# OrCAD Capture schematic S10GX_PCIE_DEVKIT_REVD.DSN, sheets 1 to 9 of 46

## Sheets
1 Title, Note, Block Diagram: title: Stratix 10 GX FPGA Development Kit; rev: D1; note: 150-0321309-D1      (6XX-44484R)
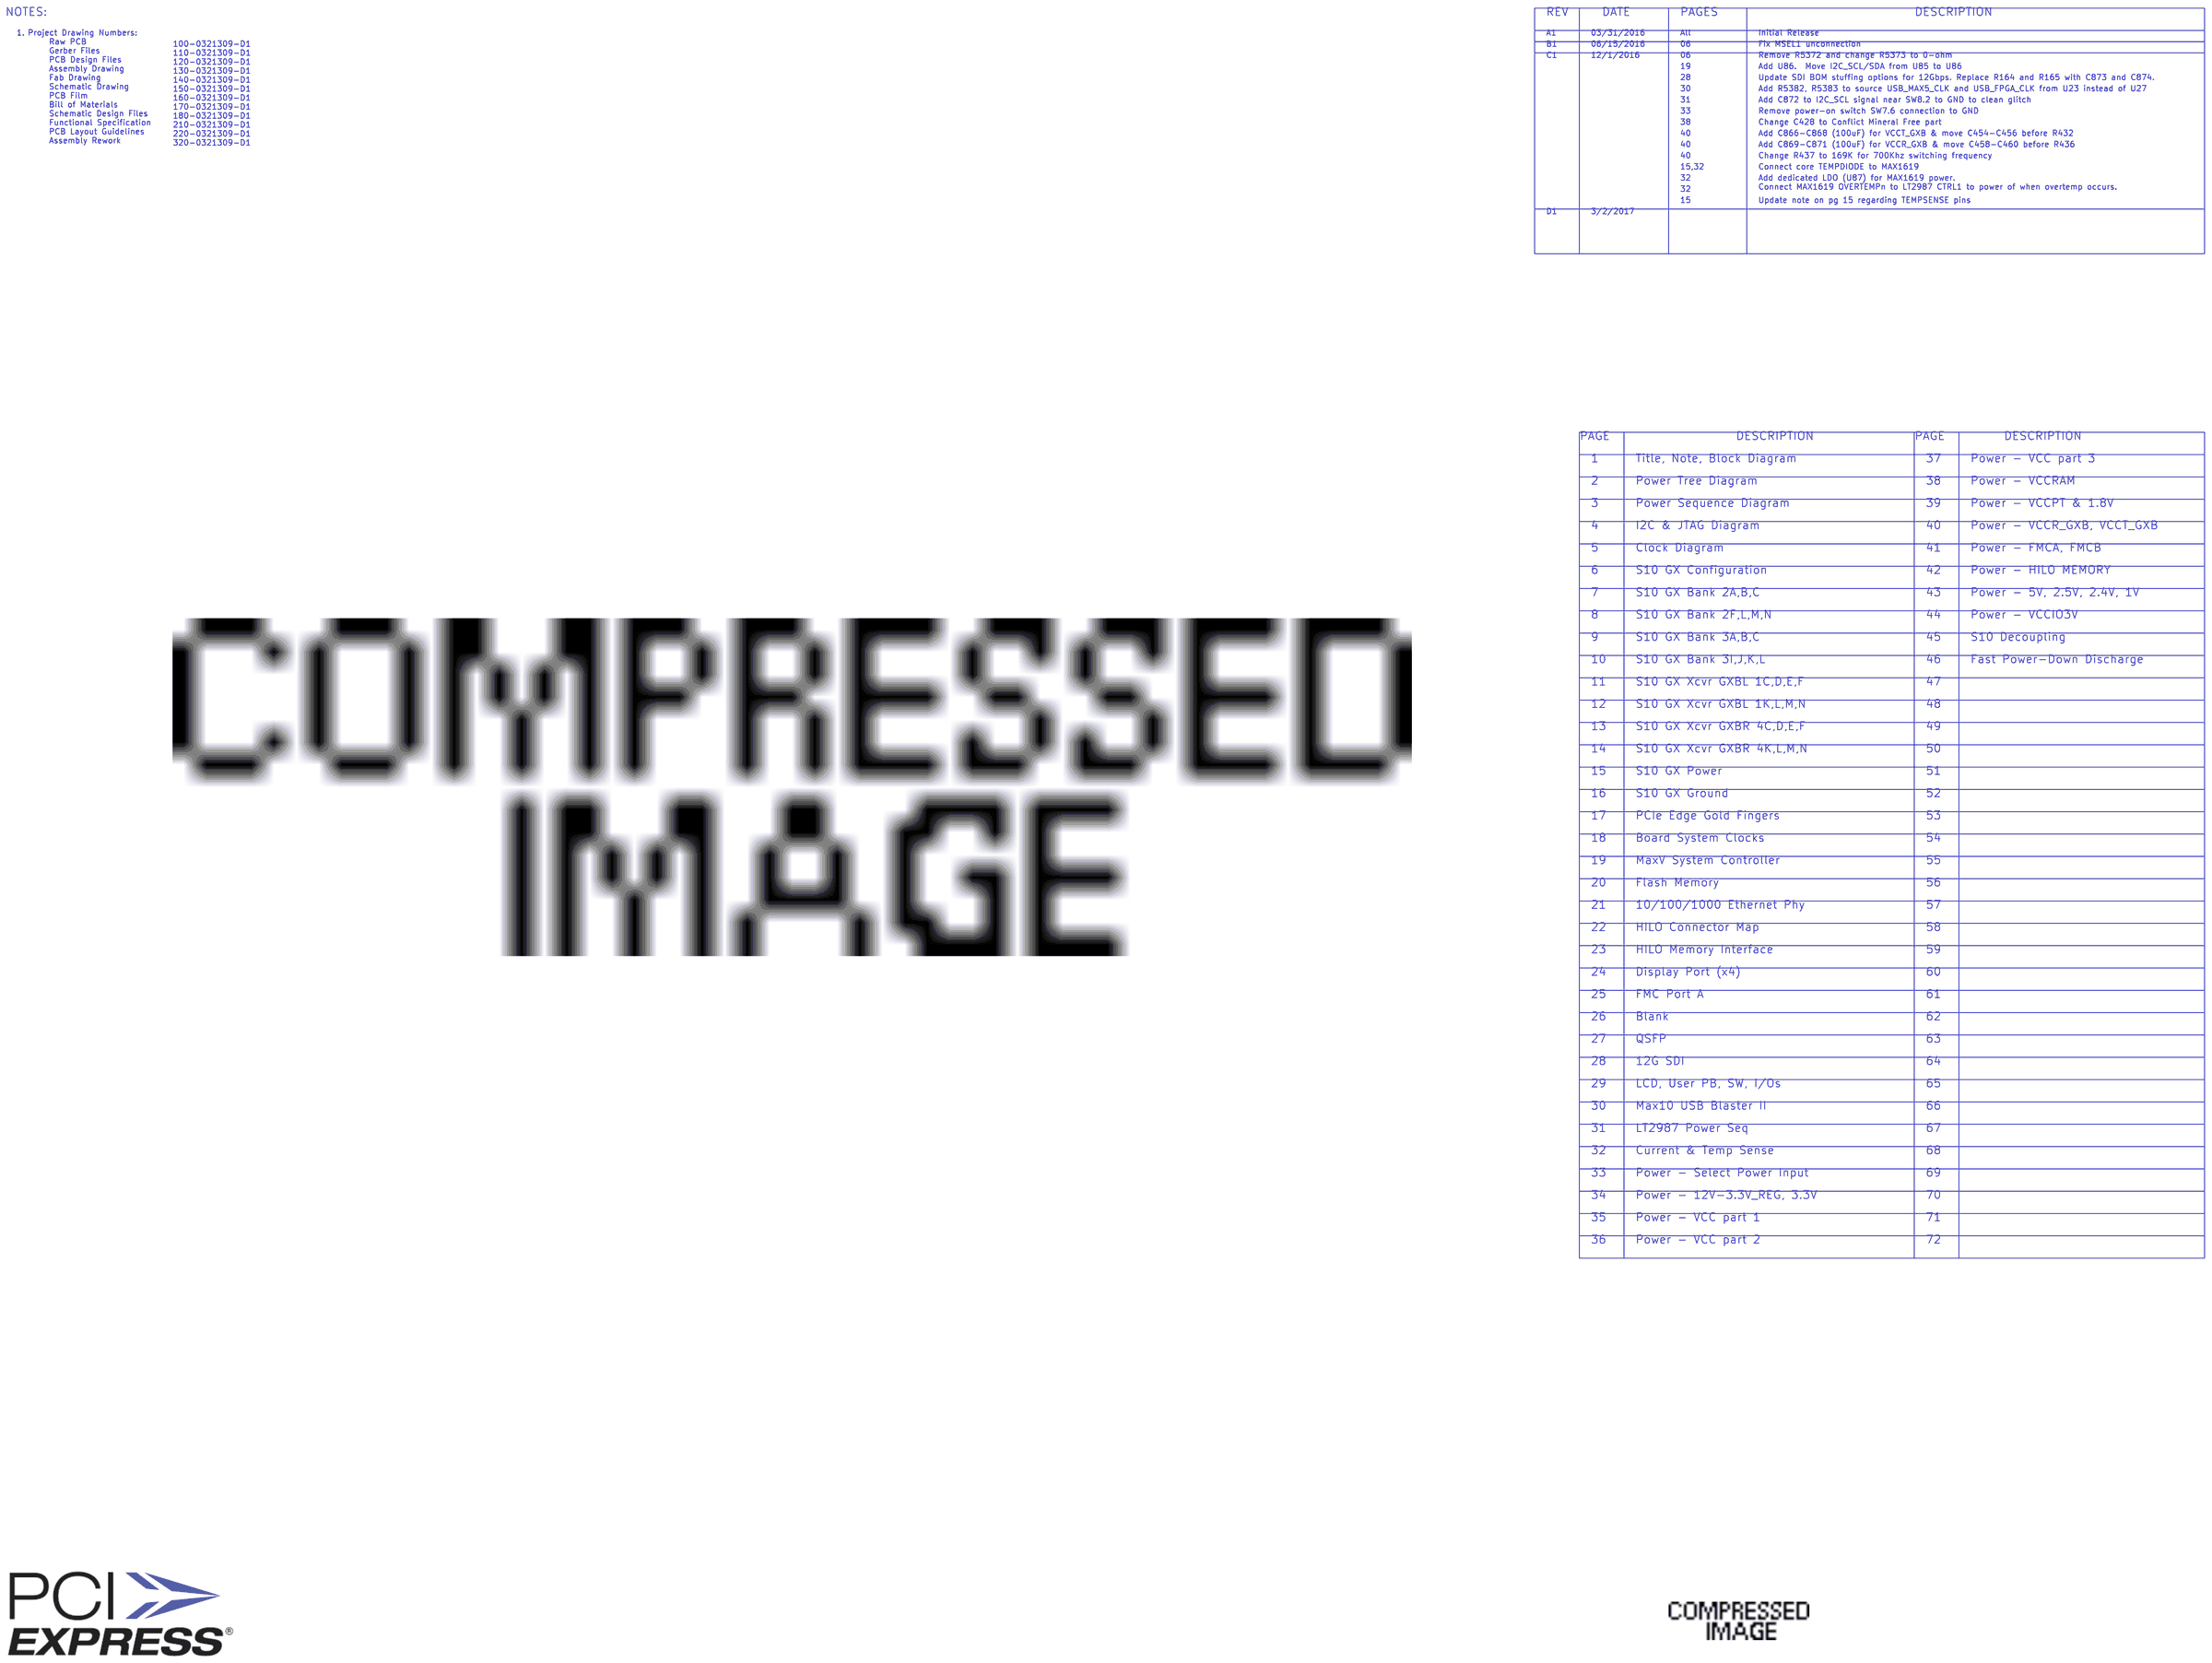
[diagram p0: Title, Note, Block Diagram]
2 Power Tree Diagram
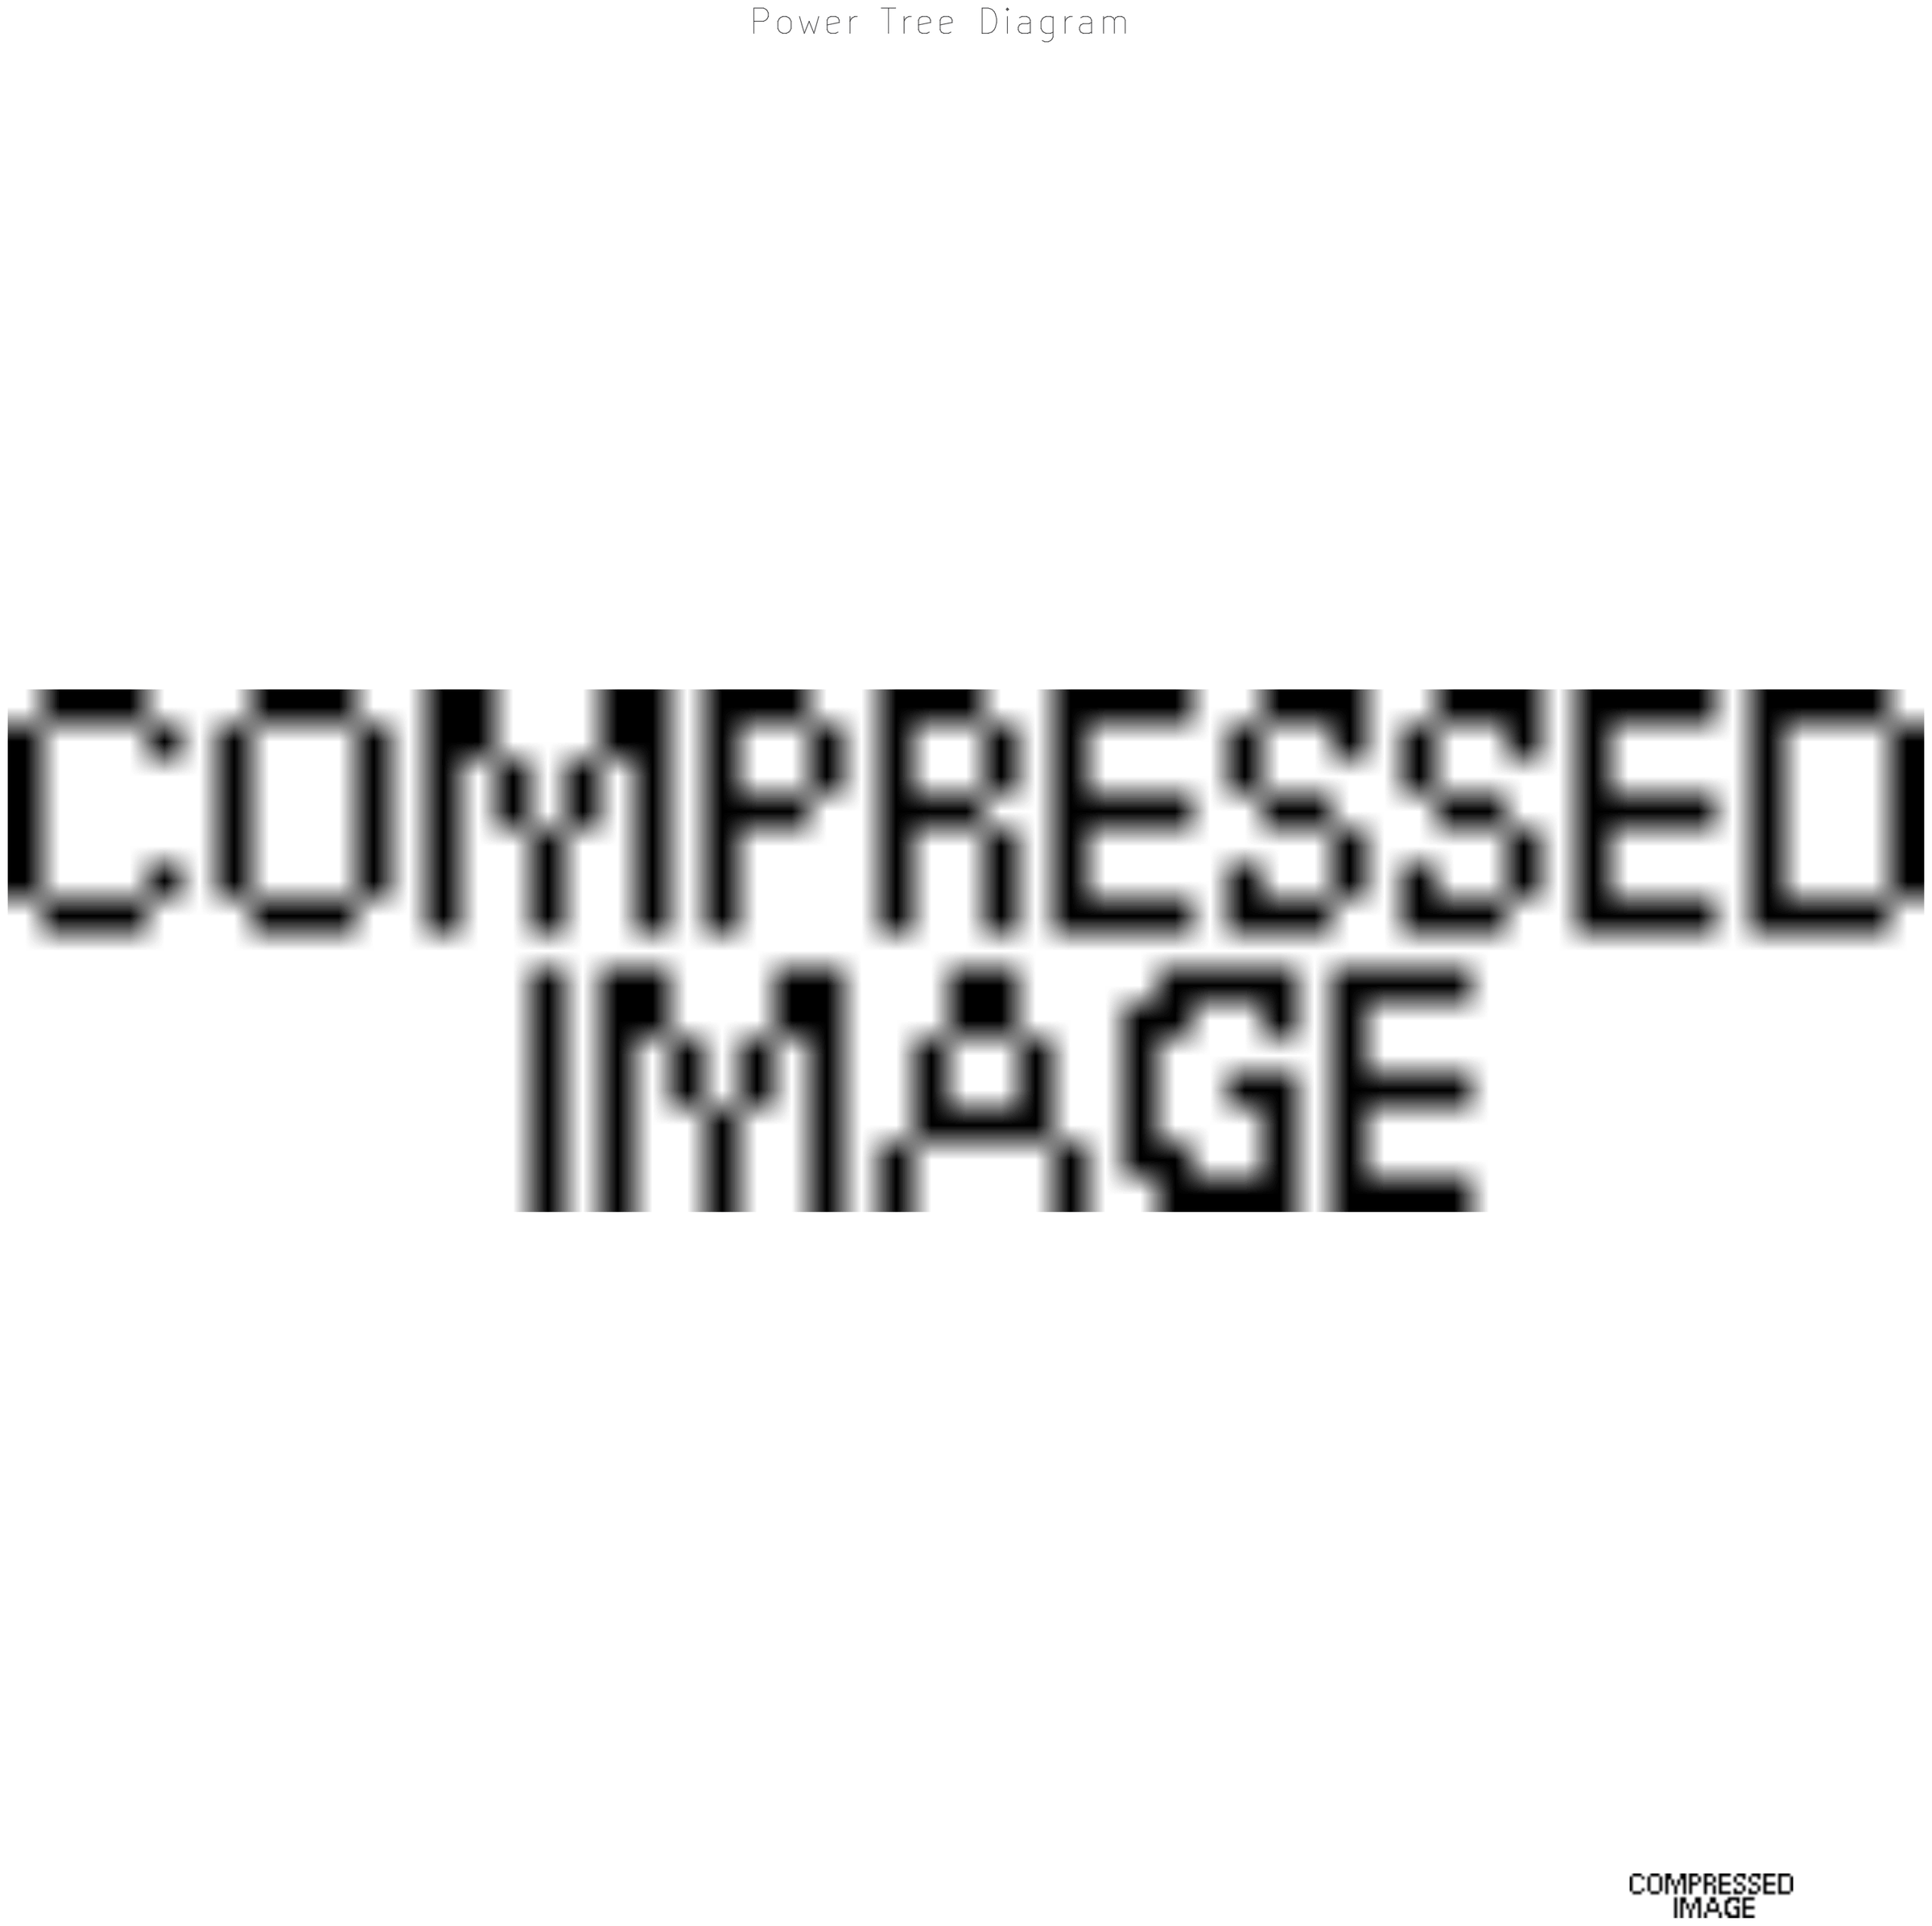
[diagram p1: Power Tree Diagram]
3 Power Sequence Diagram
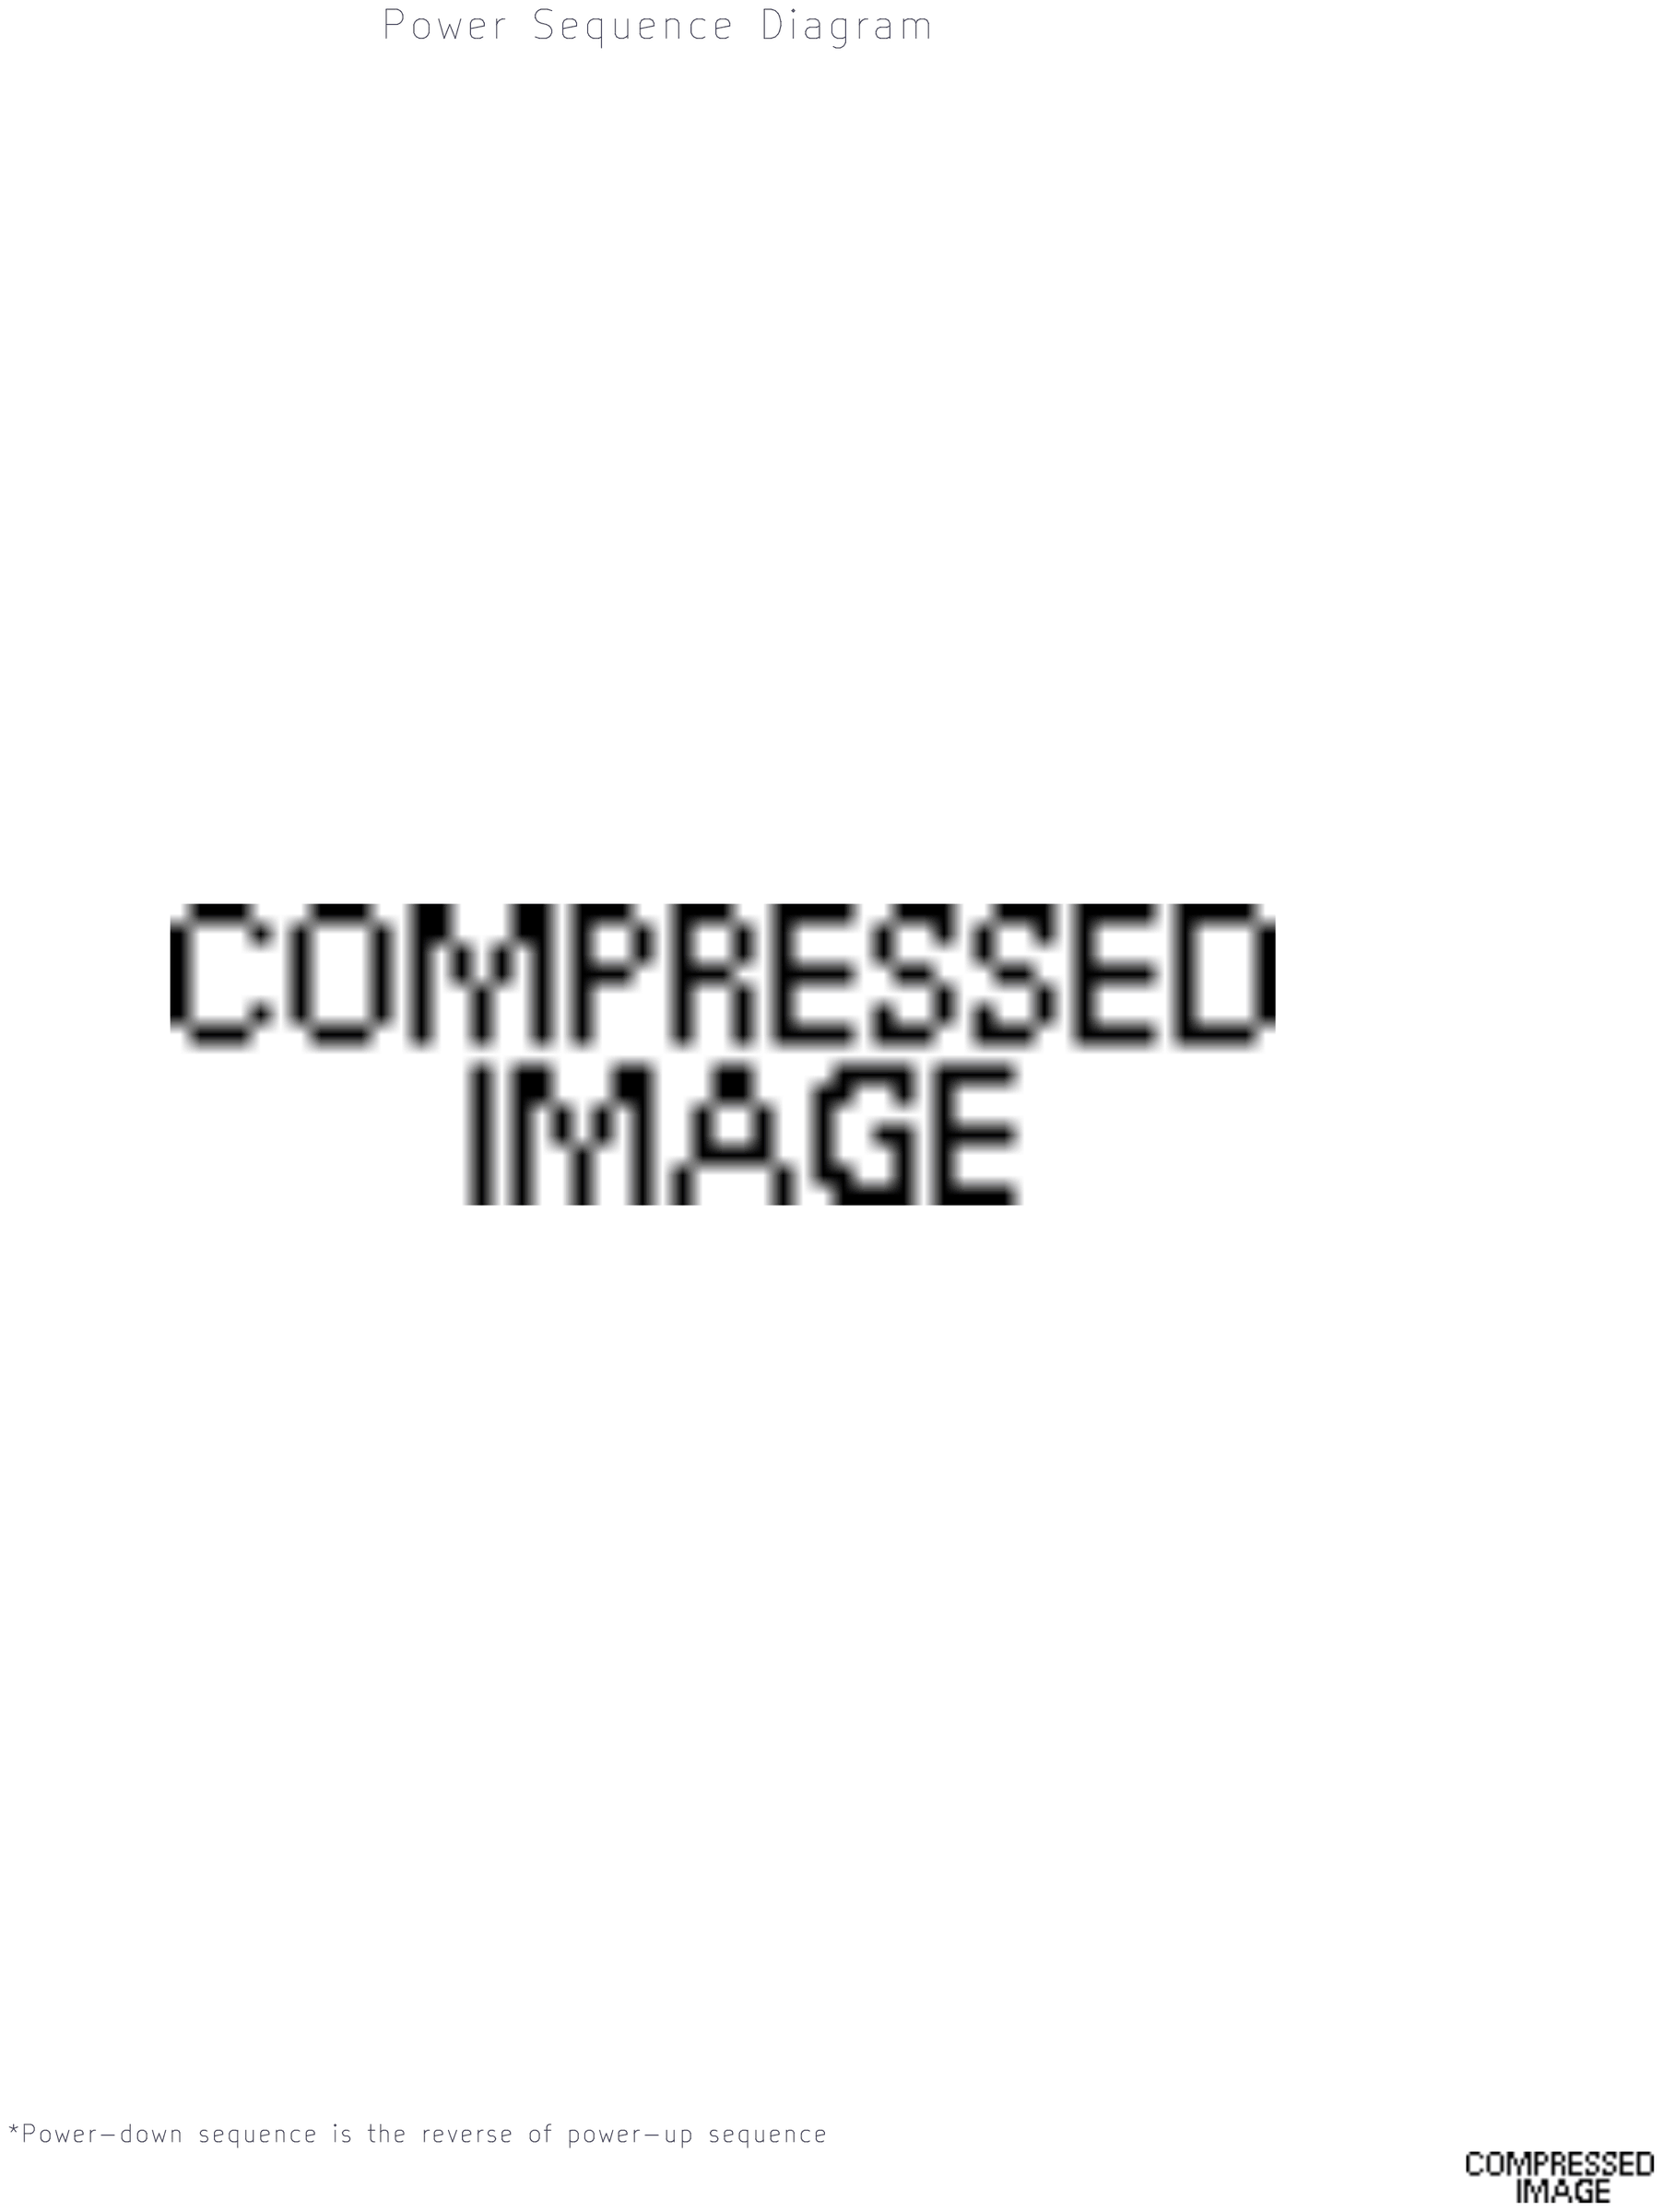
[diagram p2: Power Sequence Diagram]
4 I2C & JTAG Diagram
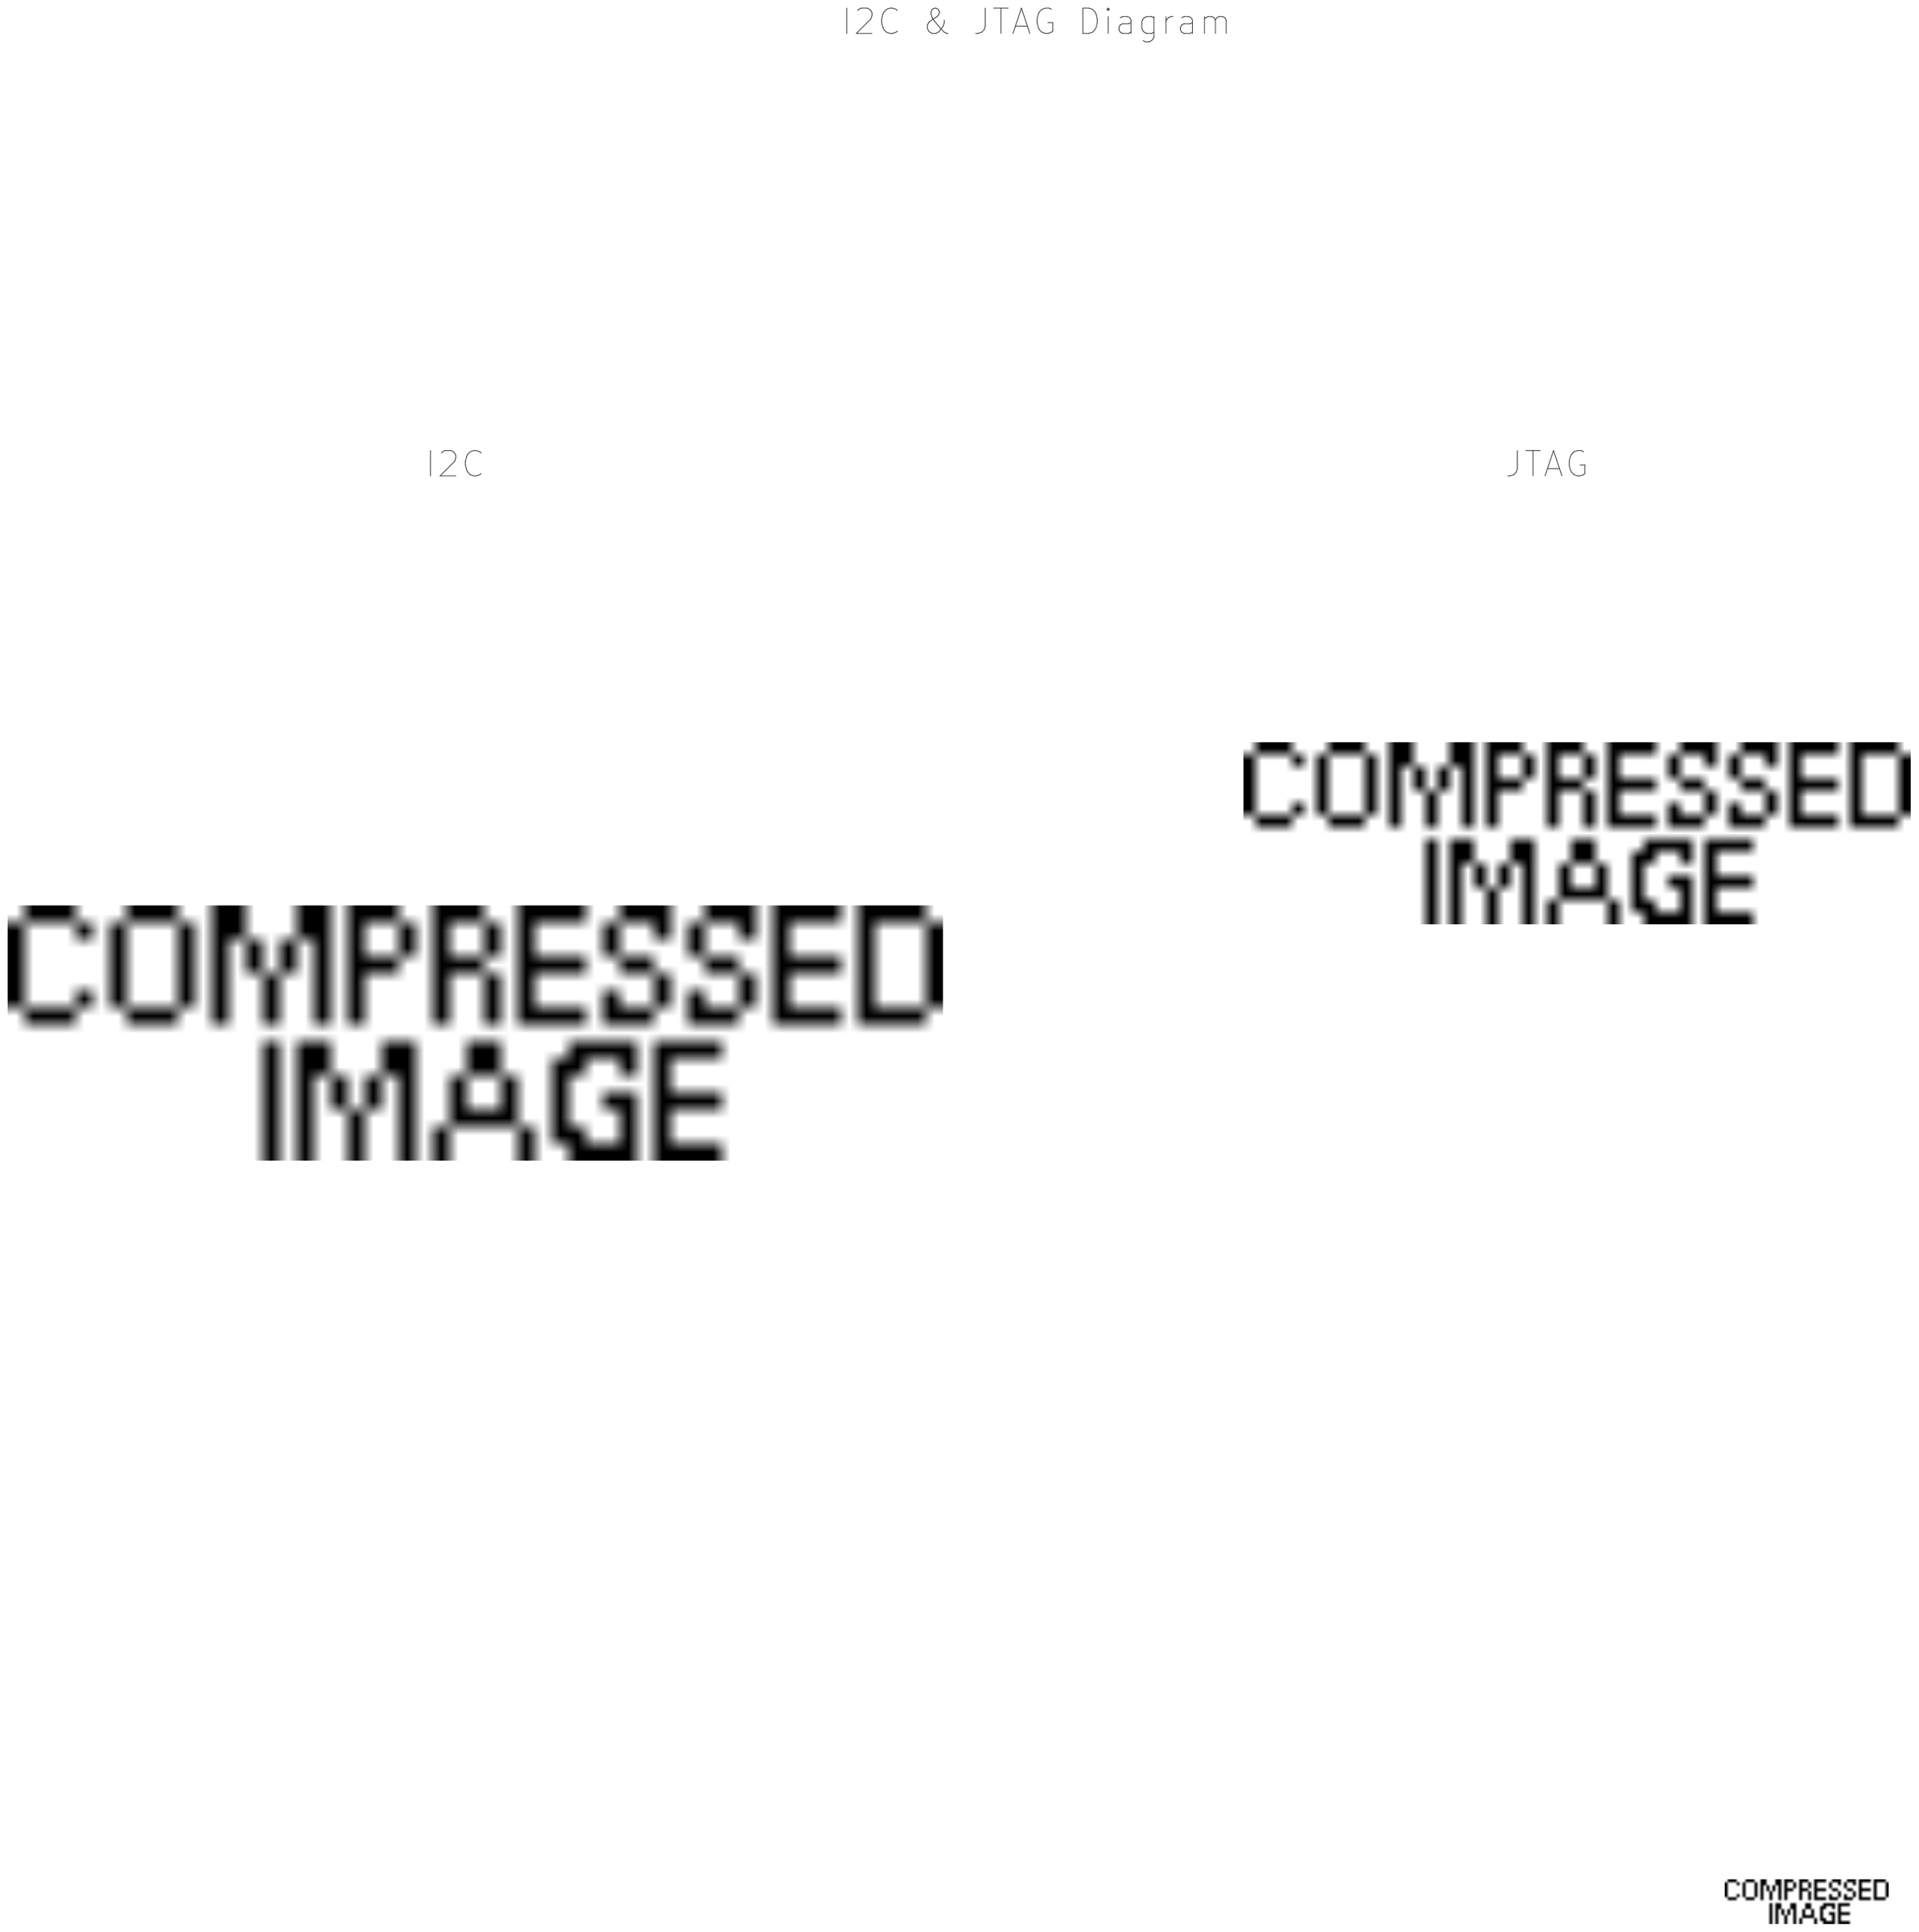
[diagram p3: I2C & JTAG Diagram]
5 Clock Diagram
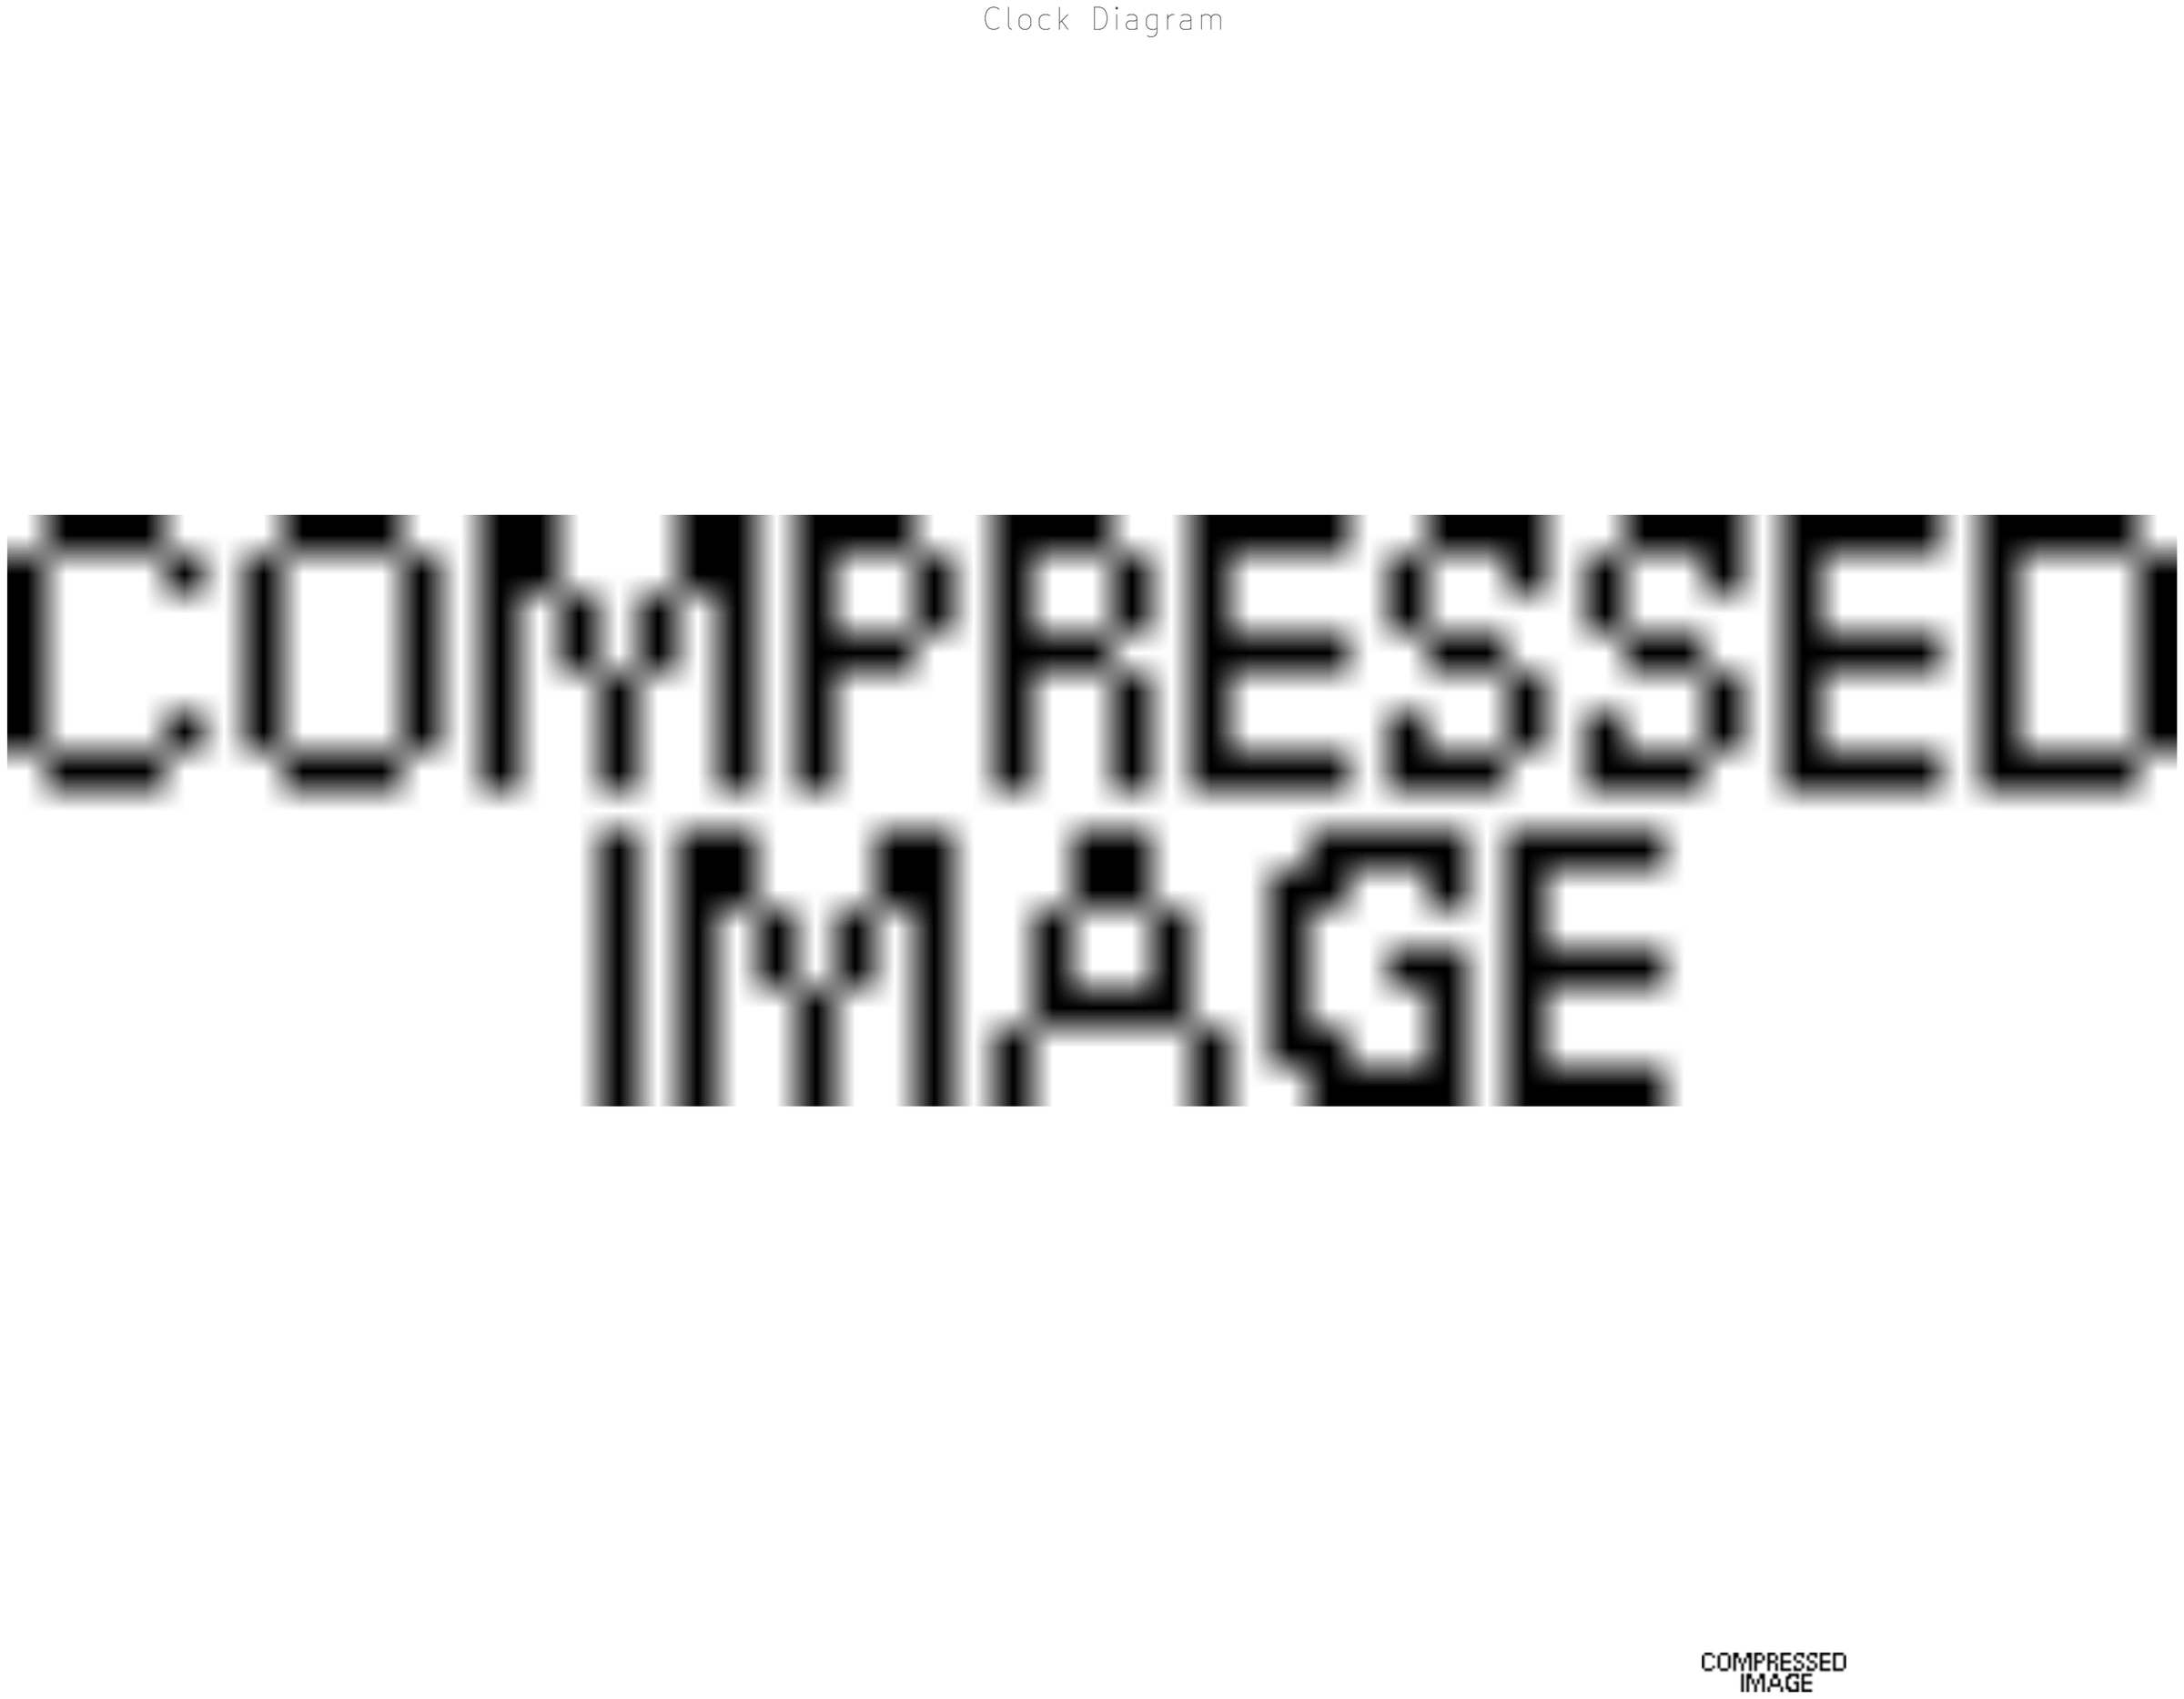
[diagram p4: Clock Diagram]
6 S10 GX Configuration: size C
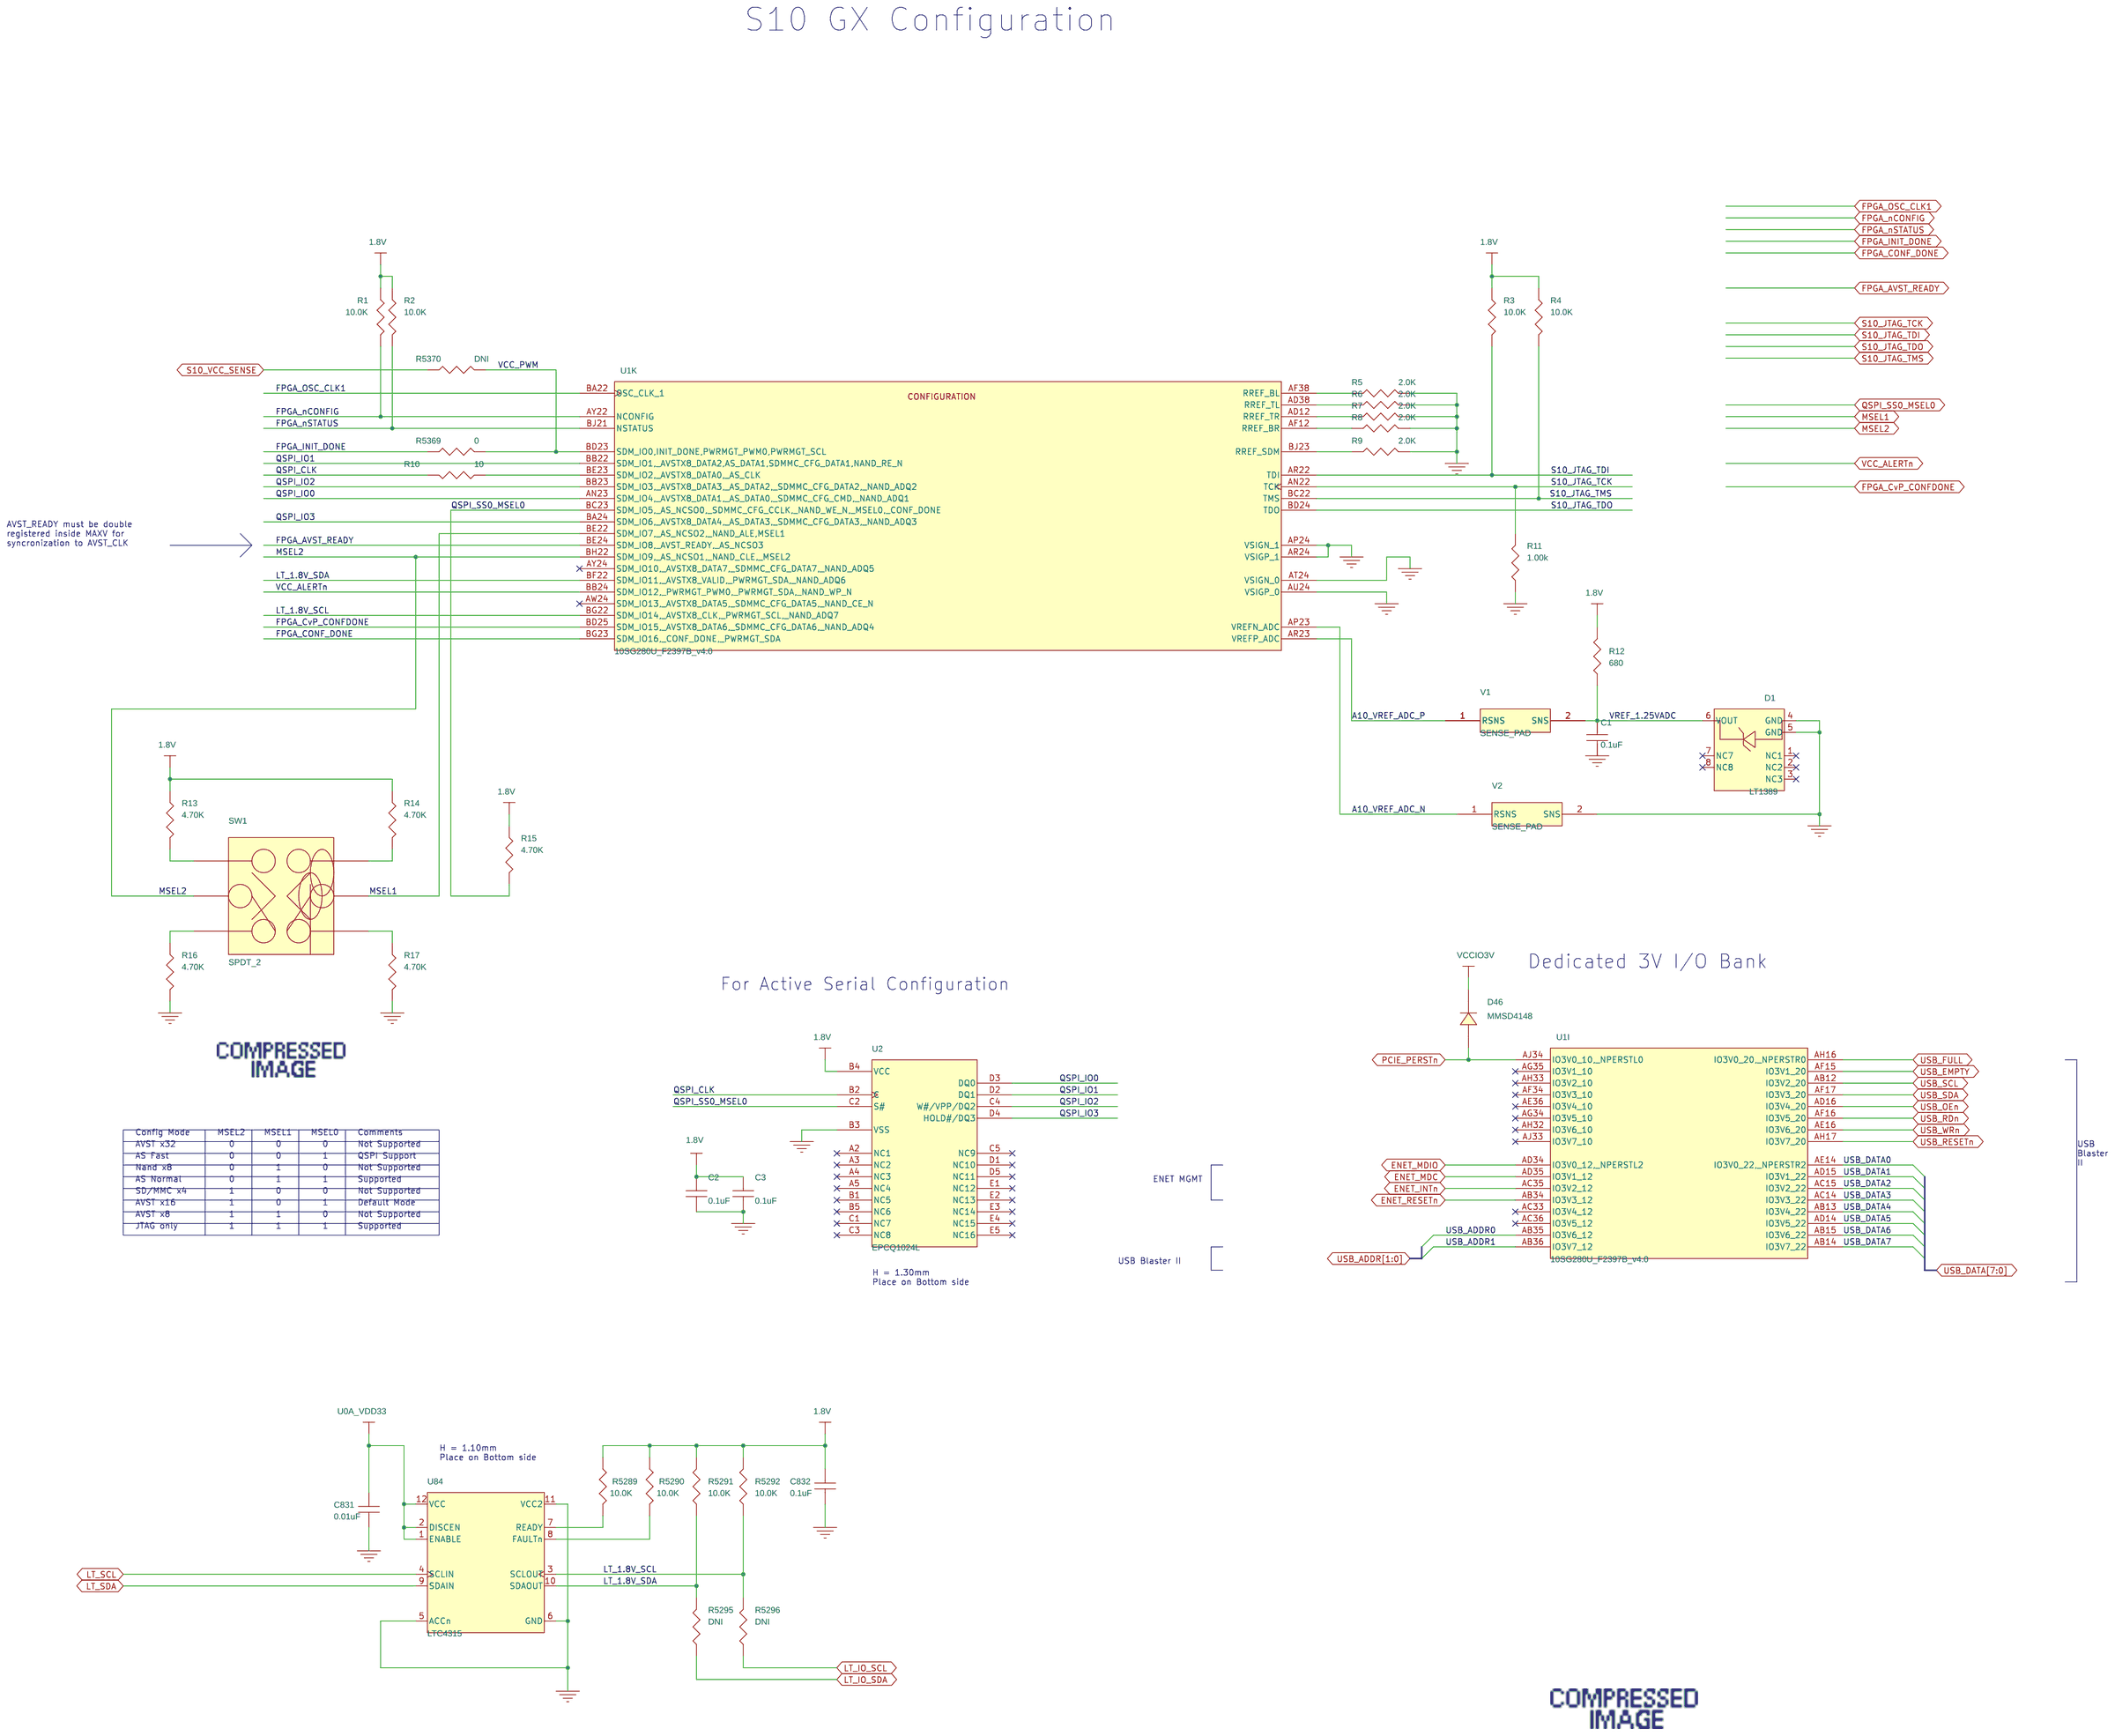
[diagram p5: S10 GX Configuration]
7 S10 GX Bank 2A,B,C: size C
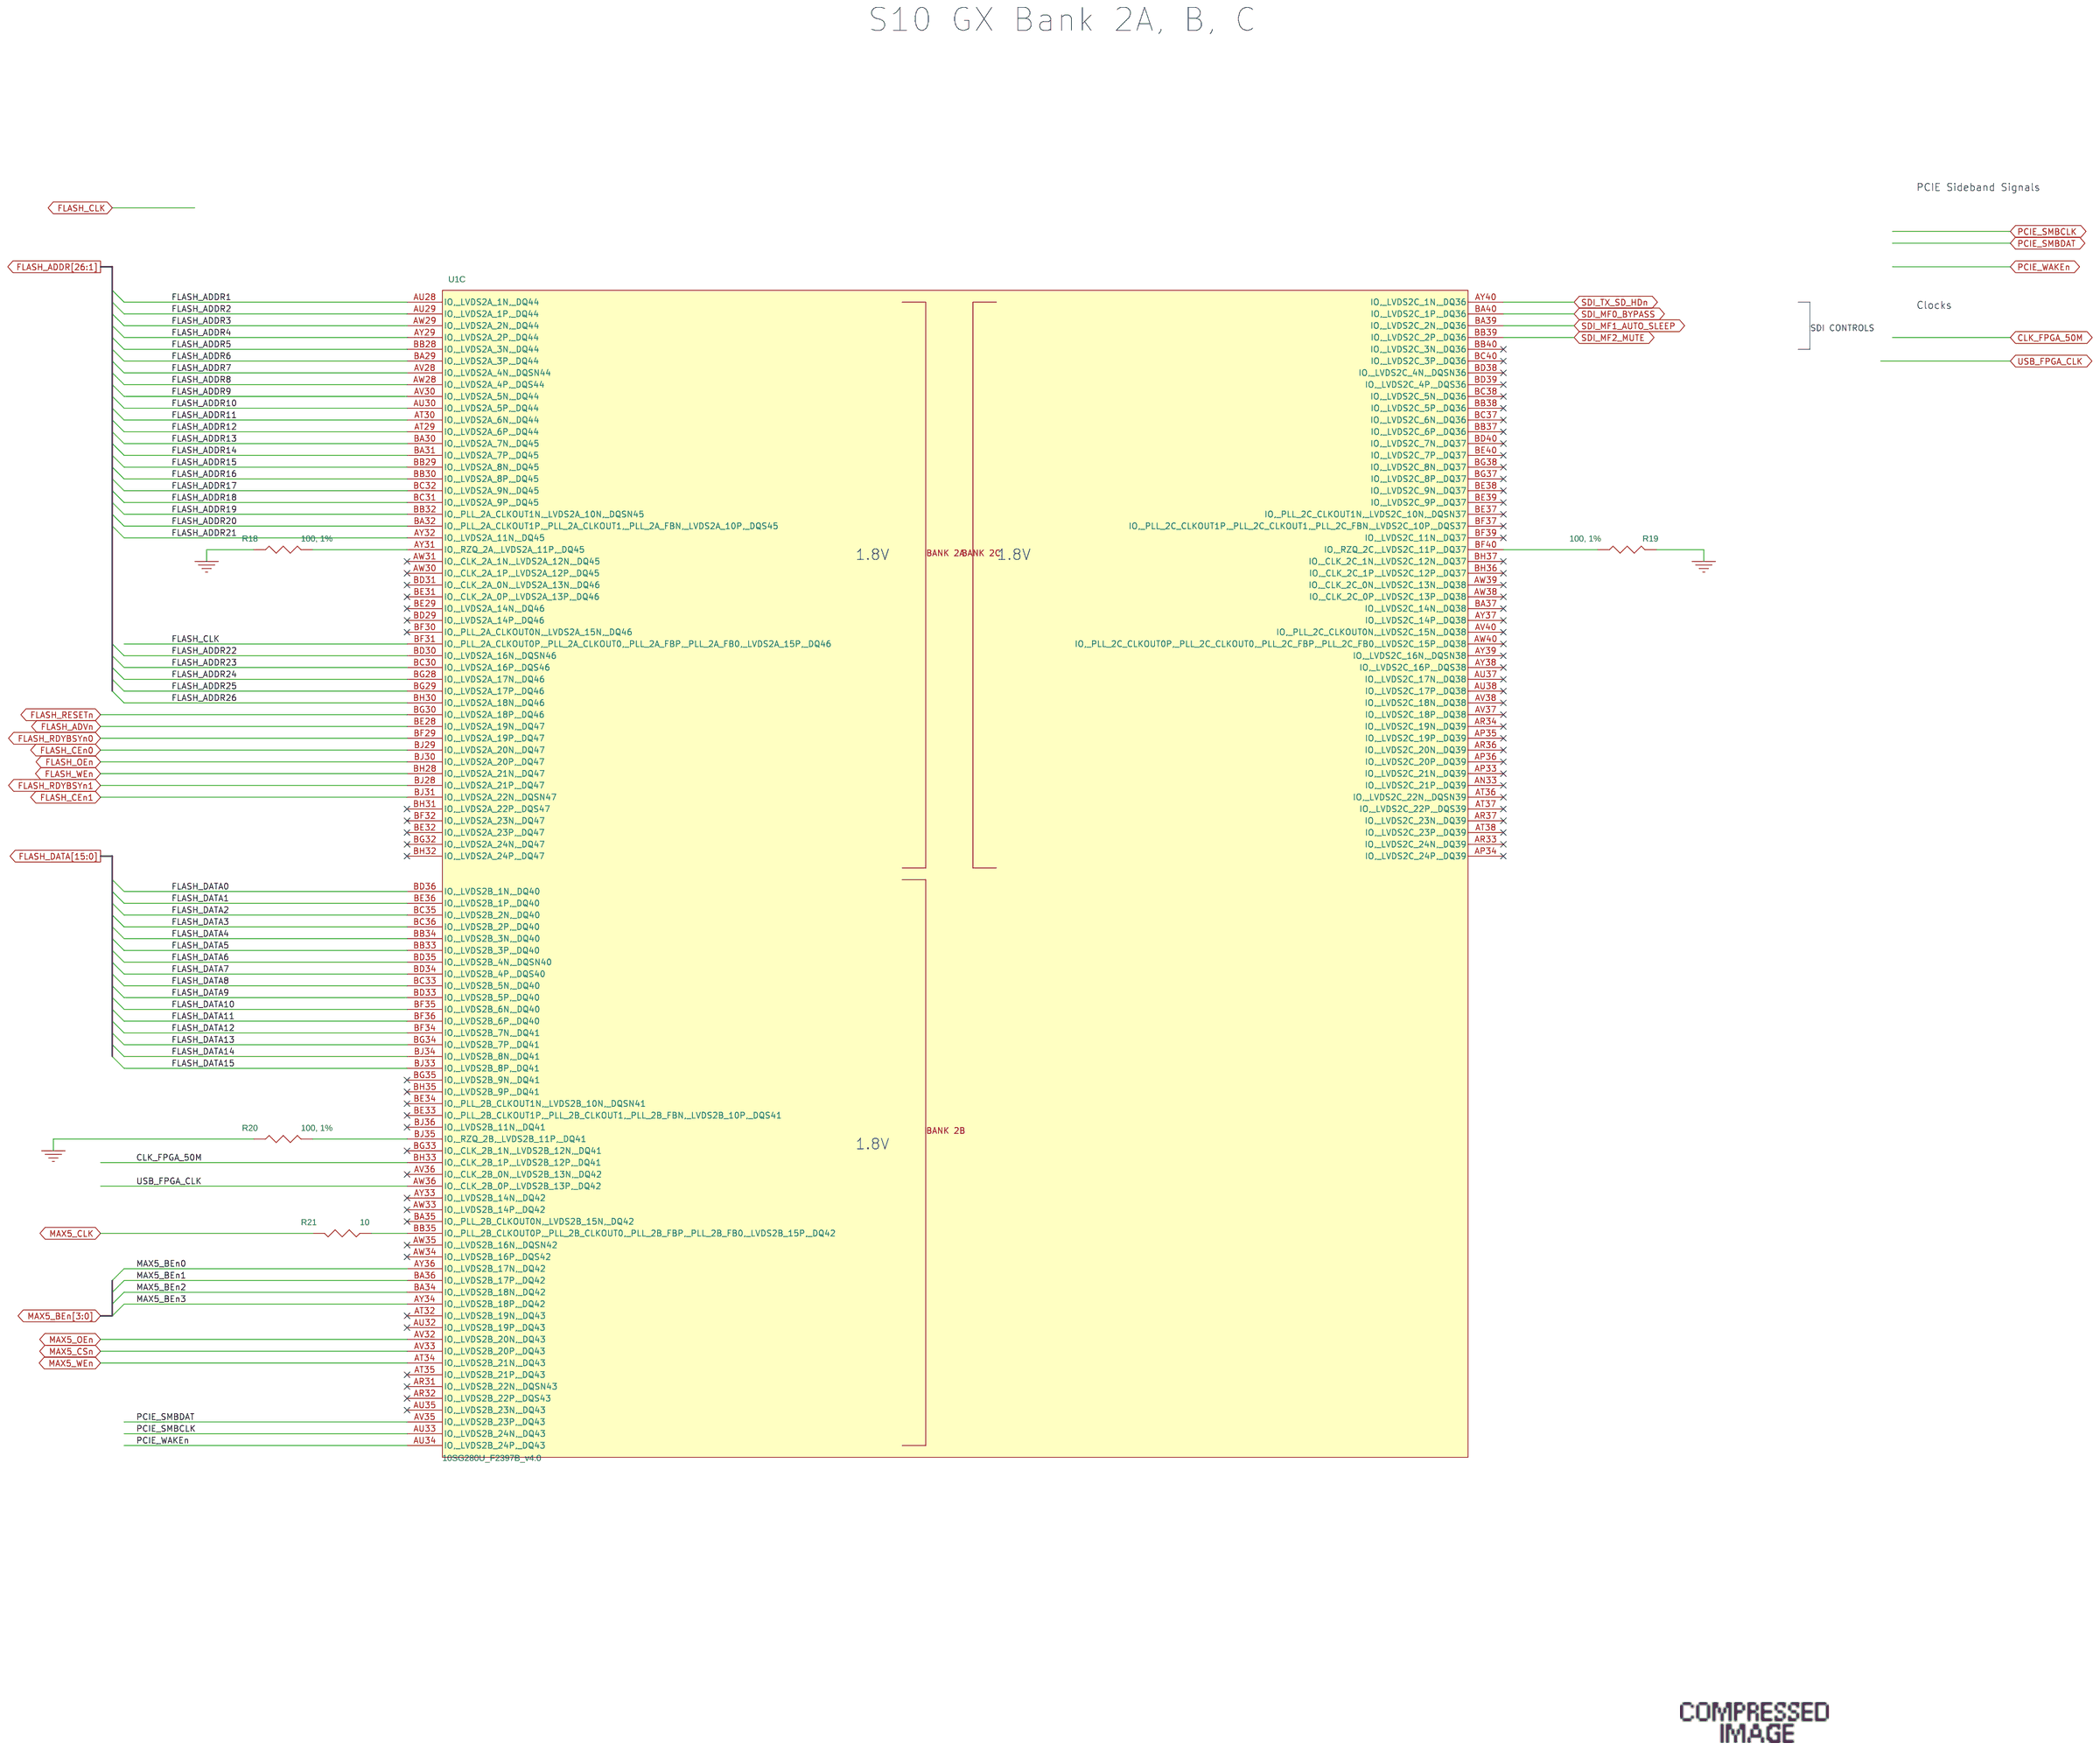
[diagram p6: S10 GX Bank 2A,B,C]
8 S10 GX Bank 2F,L,M,N: size C
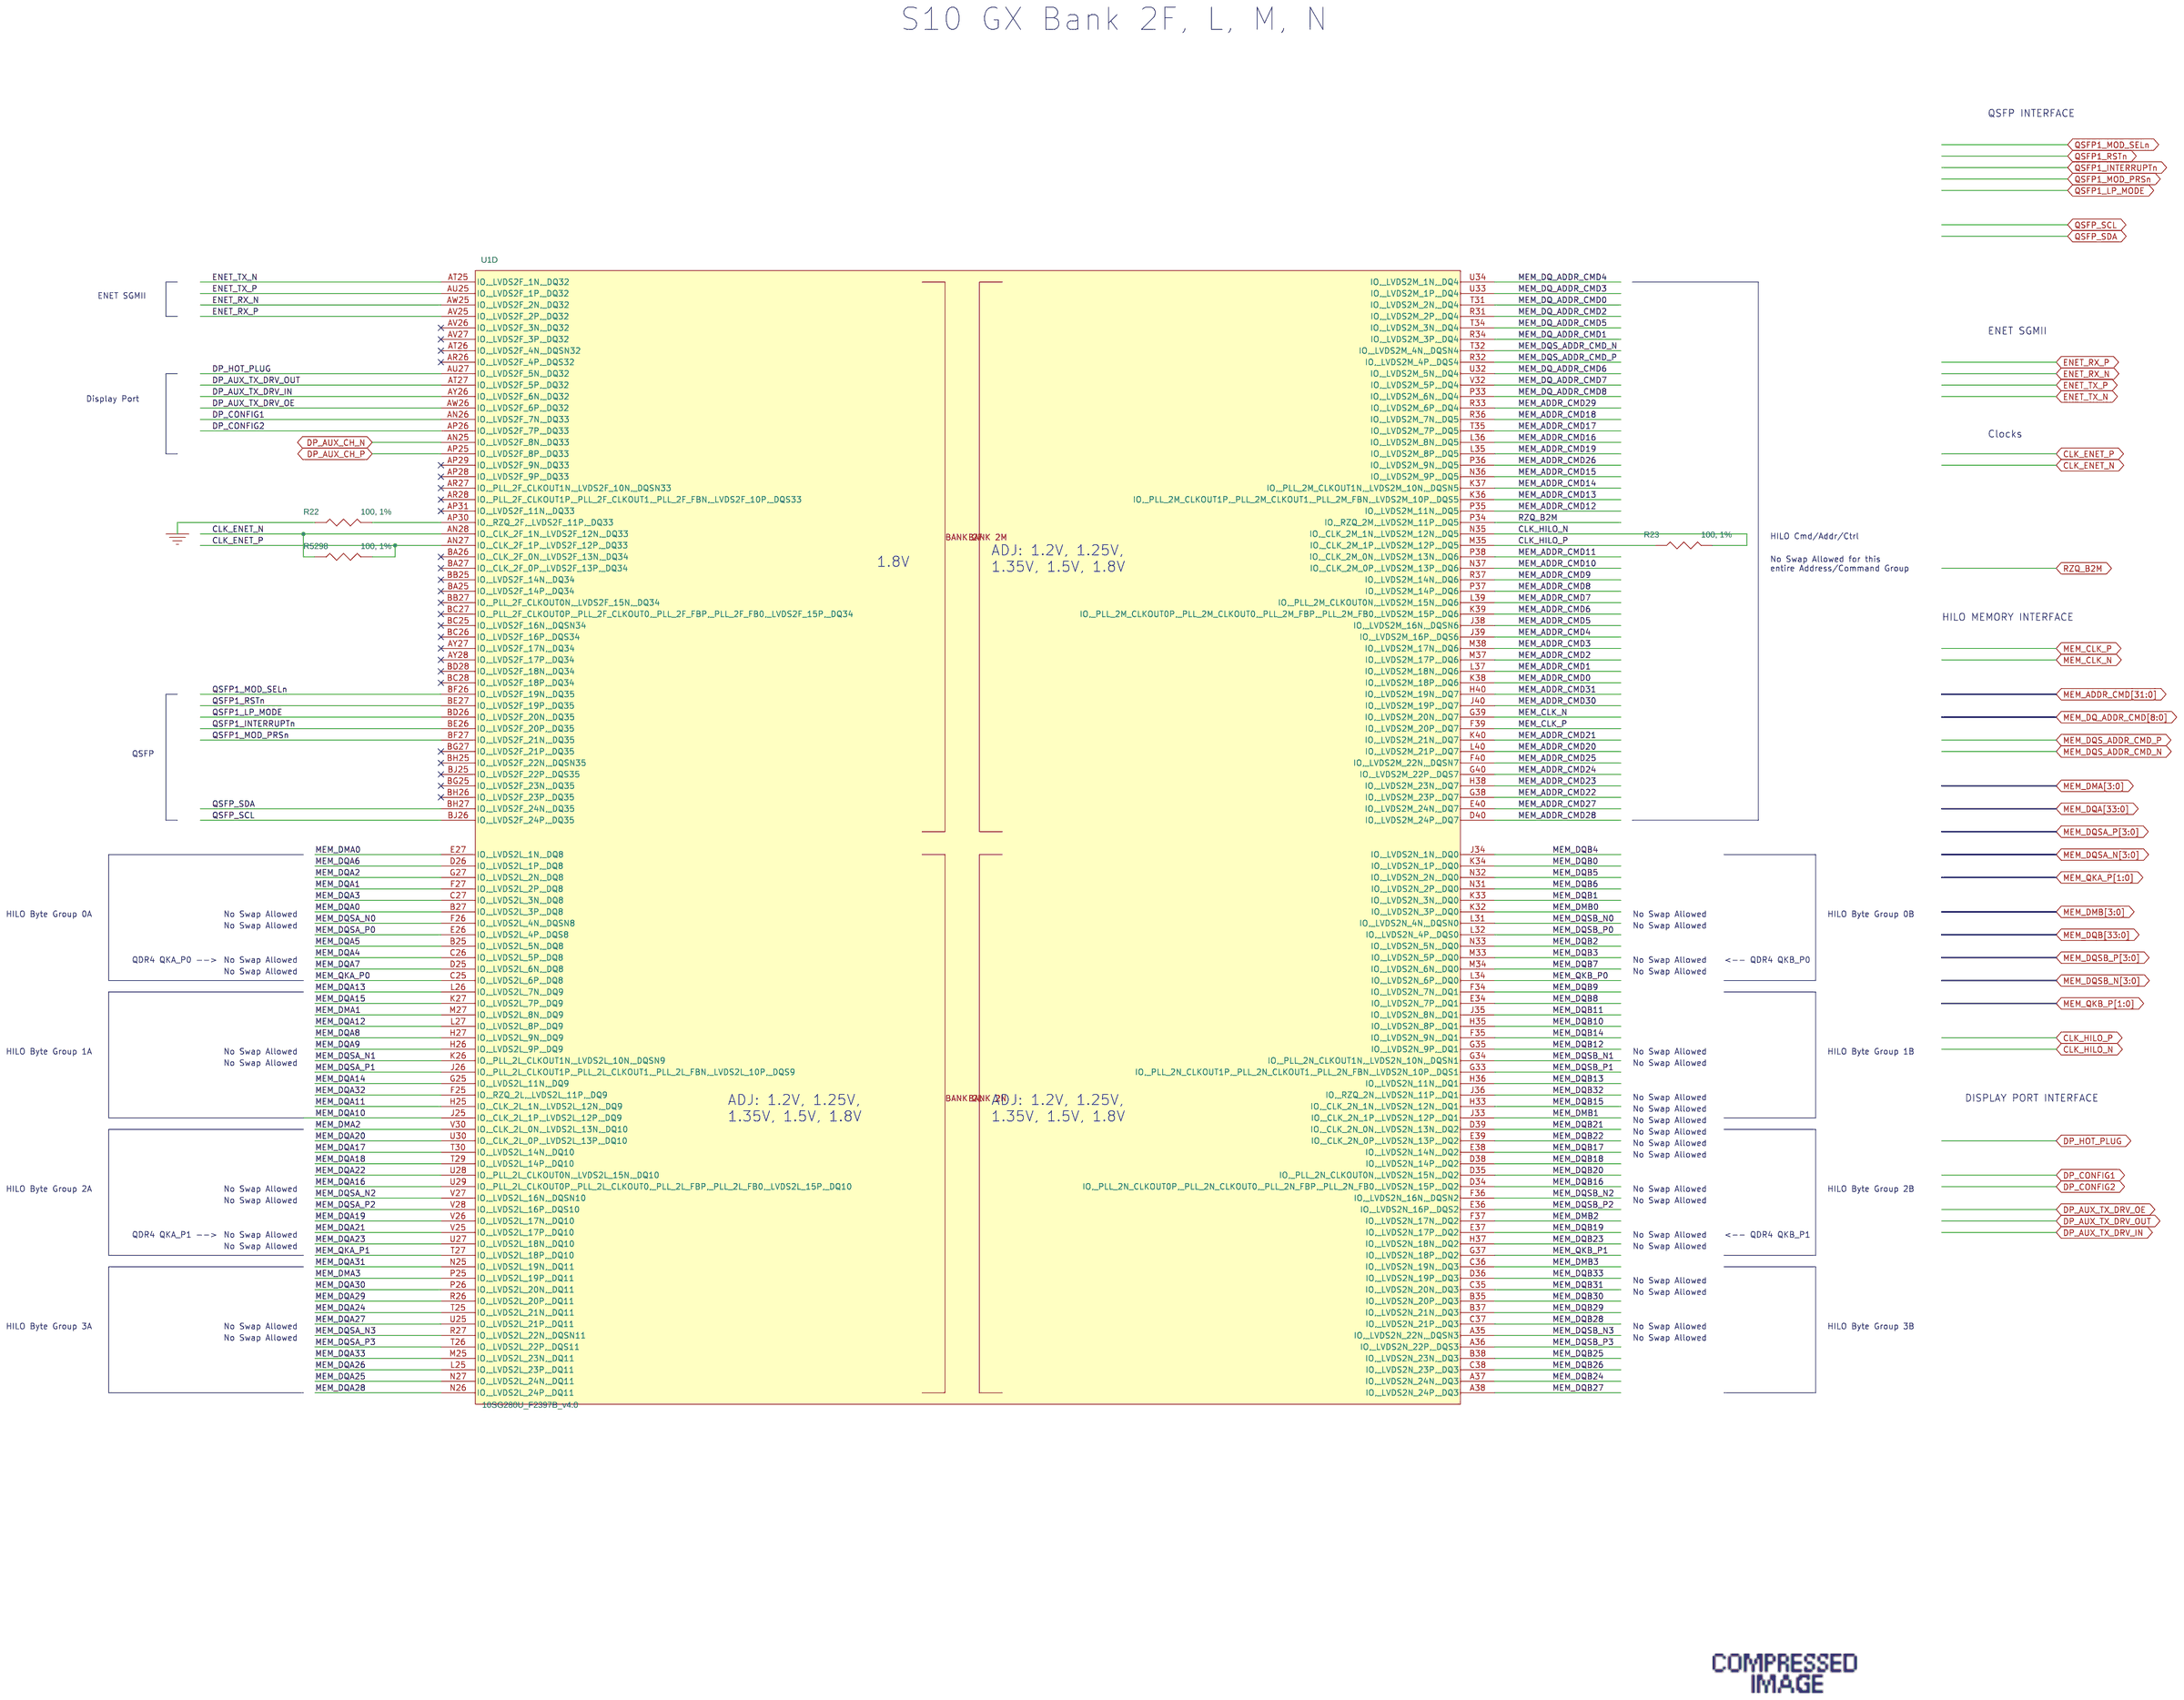
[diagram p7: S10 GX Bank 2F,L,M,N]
9 S10 GX Bank 3A,B,C: size C
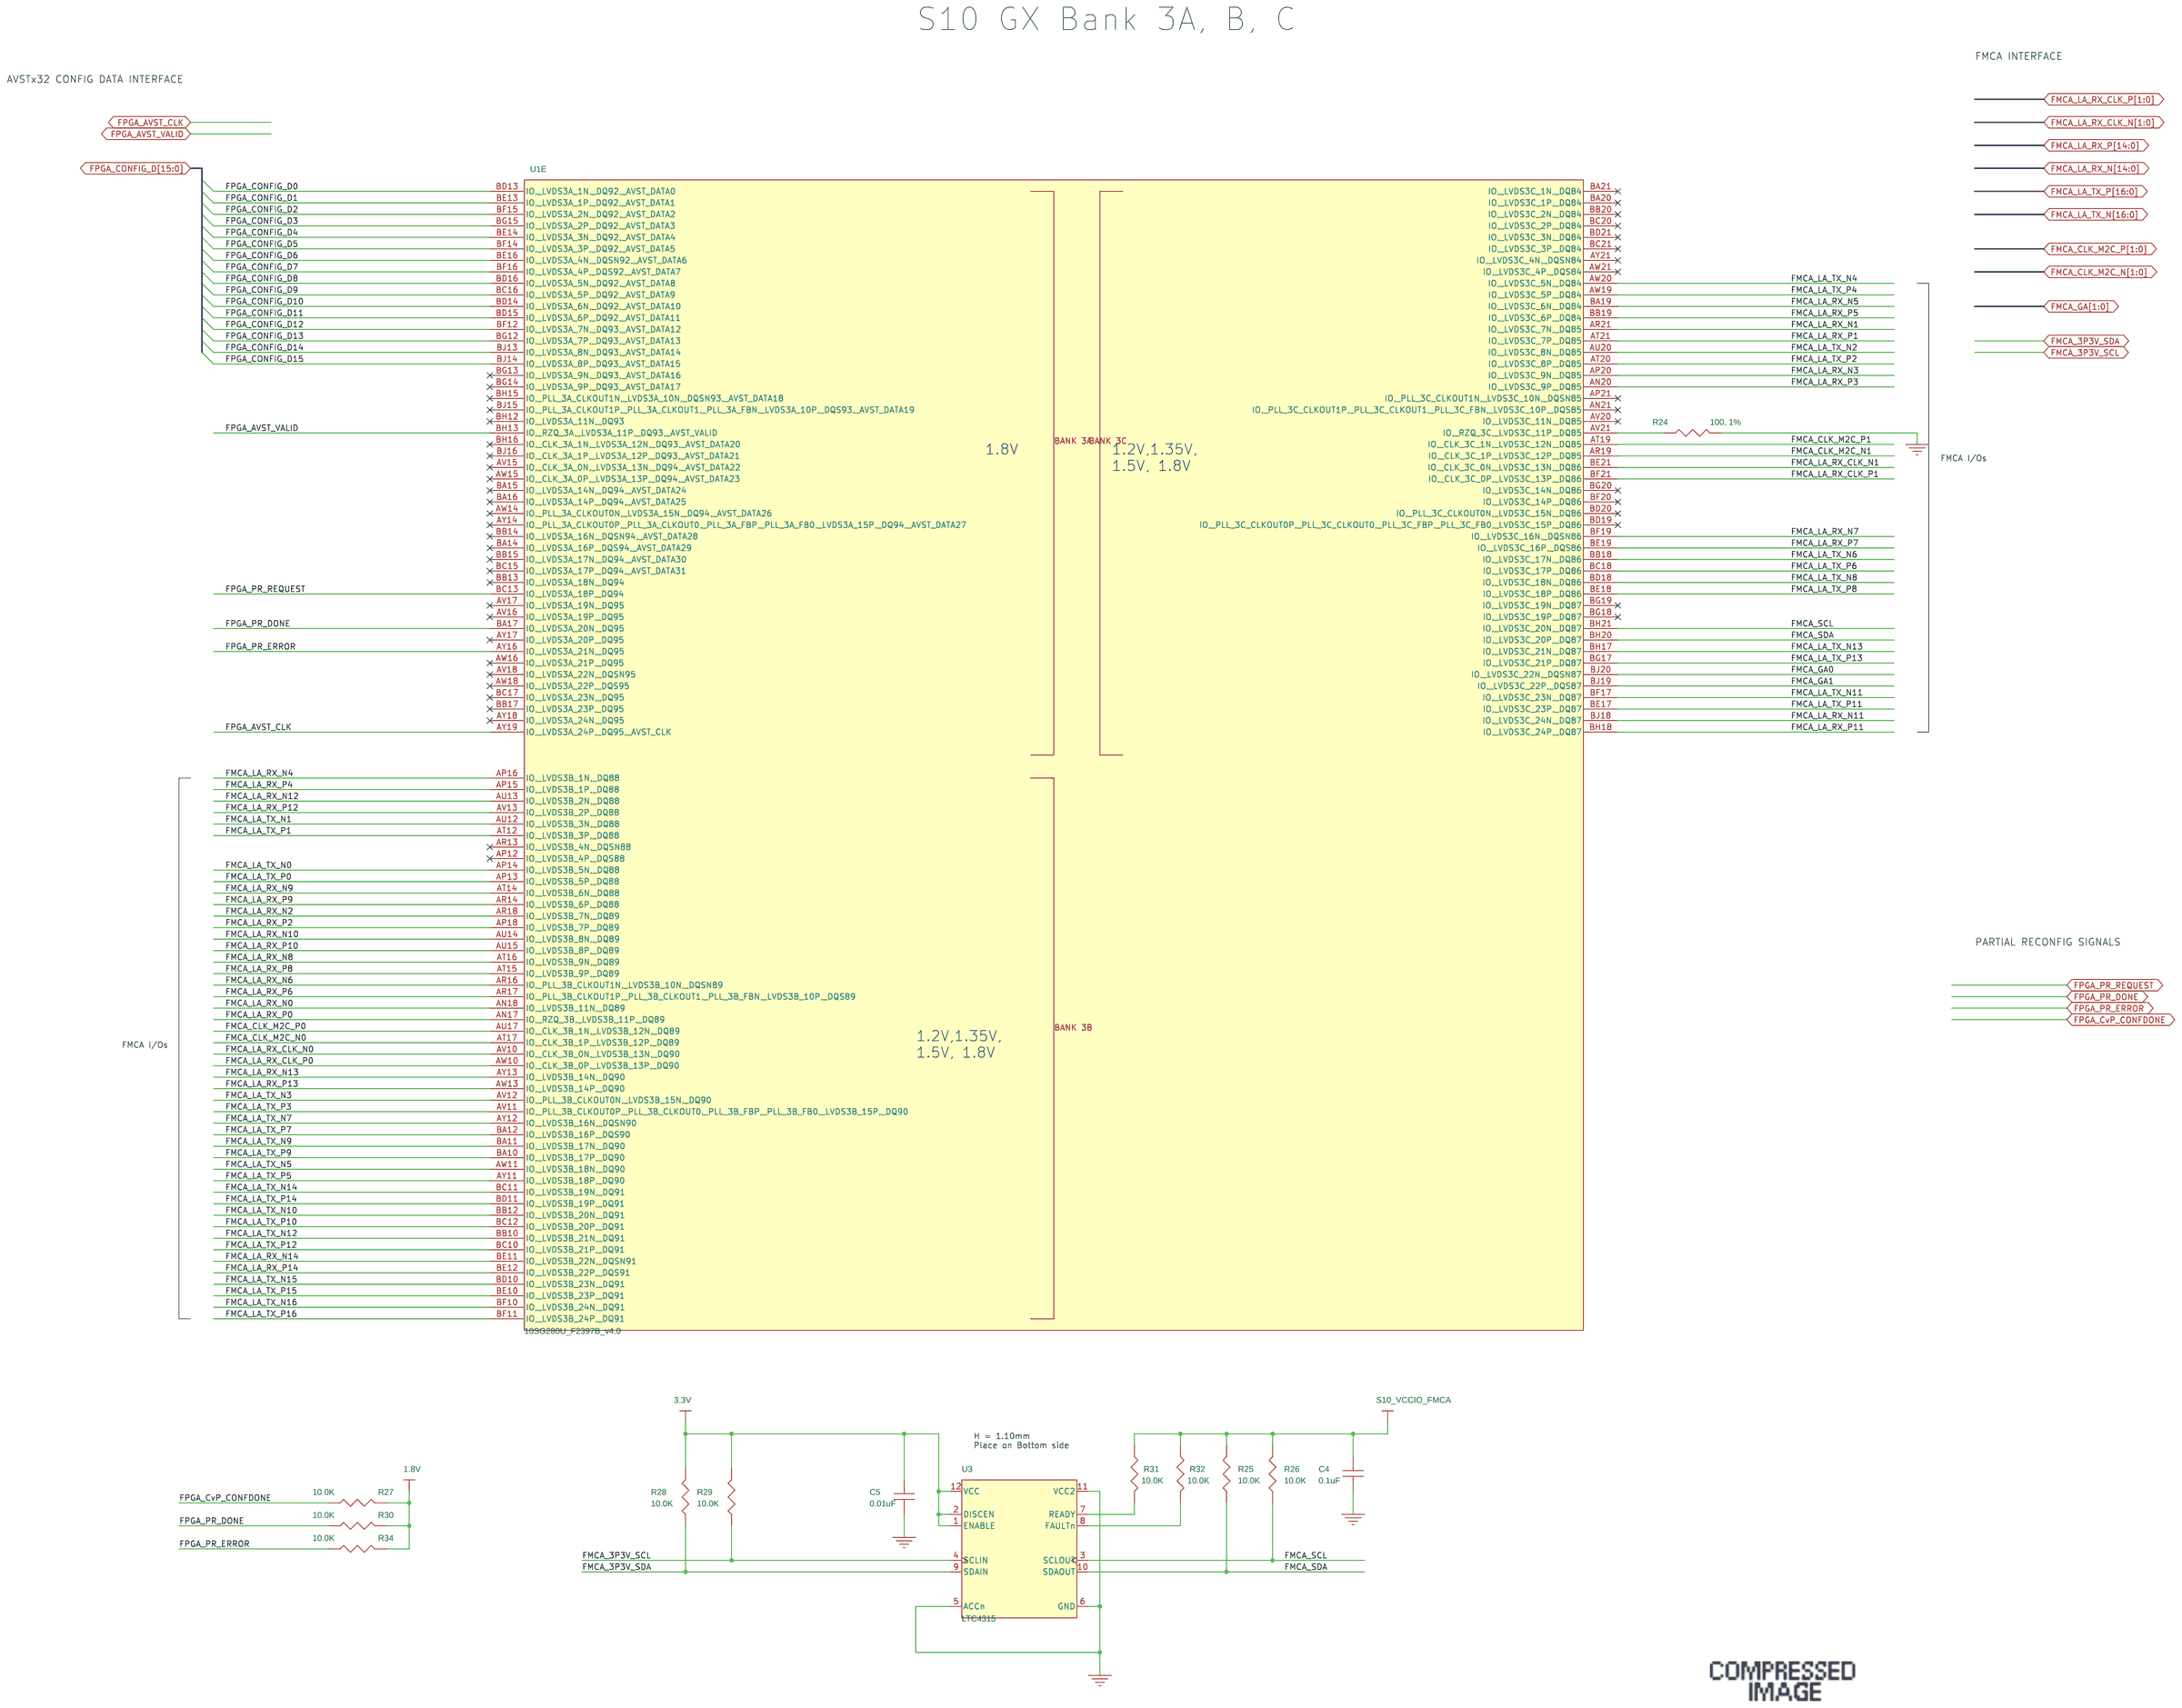
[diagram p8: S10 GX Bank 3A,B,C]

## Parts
sheet S10 GX Bank 2A,B,C
R18  100, 1%  [0402]
R19  100, 1%  [0402]
R20  100, 1%  [0402]
R21  10  [0402]
sheet S10 GX Bank 2F,L,M,N
R22  100, 1%  [0402]
R23  100, 1%  [0402]
R5298  100, 1%  [0402]
sheet S10 GX Bank 3A,B,C
C4  0.1uF  [0402]
C5  0.01uF  [0402]
R24  100, 1%  [0402]
R25  10.0K  [0402]
R26  10.0K  [0402]
R27  10.0K  [0402]
R28  10.0K  [0402]
R29  10.0K  [0402]
R30  10.0K  [0402]
R31  10.0K  [0402]
R32  10.0K  [0402]
R34  10.0K  [0402]
U3  LTC4315  [MSOP12]
sheet S10 GX Configuration
C1  0.1uF  [0402]
C2  0.1uF  [0402]
C3  0.1uF  [0402]
C831  0.01uF  [0402]
C832  0.1uF  [0402]
D1  LT1389  [SO8]
D46  MMSD4148  [SOD-123]
R1  10.0K  [0402]
R2  10.0K  [0402]
R3  10.0K  [0402]
R4  10.0K  [0402]
R5  2.0K  [0402]
R6  2.0K  [0402]
R7  2.0K  [0402]
R8  2.0K  [0402]
R9  2.0K  [0402]
R10  10  [0402]
R11  1.00k  [0402]
R12  680  [0402]
R13  4.70K  [0402]
R14  4.70K  [0402]
R15  4.70K  [0402]
R16  4.70K  [0402]
R17  4.70K  [0402]
R5289  10.0K  [0402]
R5290  10.0K  [0402]
R5291  10.0K  [0402]
R5292  10.0K  [0402]
R5295  DNI  [0402]
R5296  DNI  [0402]
R5369  0  [0402]
R5370  DNI  [0402]
SW1  SPDT_2  [SPDT_2]
U1  10SG280U_F2397B_v4.0  [BGA_F2397B]  (sections A,B,C,D,E,F,G,H,I,J,K,L,M,N,O,P,Q,R,S)
U2  EPCQ1024L  [T-PBGA-24_6x8mm]
U84  LTC4315  [MSOP12]
V1  SENSE_PAD  [SENSE]
V2  SENSE_PAD  [SENSE]

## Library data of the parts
R18-R20 R22-R24 R5298 = RESISTOR: RES,100 OHMS,1.0%,1/16W,0402; Item Num: P02-11381R; Lead Free Status: No; Manufacturer: Panasonic; Manufacturer Part Num: ERJ-2RKF1000X; Num Pins: 2; Part Class: Resistors; Price: 0; RoHS Compliant: Yes; Tolerance: 1%
R10 R21 = RESISTOR: RES, 10 OHM, 1%, 1/16W, 0402; AGILE_LINK: http://sj-agile9app/Agile/PLMServlet?action=OpenEmailObject&classid=10000&objid=146932246; Item Num: P02-16268R; LIFECYCLE_PHASE: Active; MFR_LIFECYCLE: Active; Manufacturer: Panasonic; Manufacturer Part Num: ERJ-2RKF10R0X; Num Pins: 2; PART_SUBCLASS: RESISTORS; POWER: 1/16W; RoHS Compliant: RoHS Compliant; TOLERANCE: +/-1%
C4 C832 = CAP: CAP - CERAMIC,  0.1UF 0402 25VDC Y5V; Dielectric: Y5V; Item Num: P03-15057R; LIFECYCLE_PHASE: Active; Lead Free Status: Lead Free; MFR_LIFECYCLE: Active; Manufacturer: Murata; Manufacturer Part Num: GRM155F51E104ZA01D; Num Pins: 2; PART_SUBCLASS: CAPACITORS; Part Class: CAPACITORS; RATED_VOLTAGE: 25V; RoHS Compliant: RoHS Compliant; TOLERANCE: +80%/-20%
C5 C831 = CAP: CAP, CER .01UF 16V X7R 0402; AGILE_LINK: http://sj-agile9app/Agile/PLMServlet?action=OpenEmailObject&classid=10000&objid=242850622; Item Num: P03-15137R; LIFECYCLE_PHASE: Active; MFR_LIFECYCLE: Active; Manufacturer: Murata; Manufacturer Part Num: GRM155R71C103KA01D; Num Pins: 2; PACKAGING: Tape & Reel (TR); PART_SUBCLASS: CAPACITORS; RATED_VOLTAGE: 16V; RoHS Compliant: RoHS Compliant; TOLERANCE: +/-10%
R25 R26 R28 R29 R31 R32 R5289-R5292 = RESISTOR: RES,10.0K OHMS,1.0%,1/16W, 0402; Item Num: P02-11364R; Lead Free Status: No; Manufacturer: Panasonic; Manufacturer Part Num: ERJ-2RKF1002X; Num Pins: 2; Part Class: Resistors; Price: 0
R27 R30 R34 = RESISTOR: RES,10.0K OHMS,1.0%,1/16W, 0402; AGILE_LINK: http://sj-agile9app/Agile/PLMServlet?action=OpenEmailObject&classid=10000&objid=146548997; Item Num: P02-11364R; LIFECYCLE_PHASE: Active; Lead Free Status: No; MFR_LIFECYCLE: Active; Manufacturer: Panasonic; Manufacturer Part Num: ERJ-2RKF1002X; Num Pins: 2; PART_SUBCLASS: RESISTORS; POWER: 1/16W; RoHS Compliant: Yes; TOLERANCE: +/-1%
U3 U84 = LTC4315: Item Num: P01-17868R; Manufacturer Part Num: LTC4315CMS#PBF
C1-C3 = CAP: CAP - CERAMIC,  0.1UF 0402 25VDC Y5V; Dielectric: X5R; Item Num: P03-15057R; LIFECYCLE_PHASE: Active; Lead Free Status: Lead Free; Manufacturer: Murata; Manufacturer Part Num: GRM155F51E104ZA01D; Num Pins: 2; Part Class: CAPACITORS; Price: 0.07; RoHS Compliant: RoHS Compliant; Tolerance: +80%/-20%
D1 = LT1389: DIODE - ZENER, 1.25V, S8, SMD; Item Num: P08-20828R; Manufacturer: Linear Technology; Manufacturer Part Num: LT1389ACS8-1.25
D46 = DIODE_2: DIODE, Small Signal; Item Num: P08-20034R; Lead Free Status: Yes; Manufacturer: Fairchild Semiconductor; Part Class: Diodes
R1-R4 = RESISTOR: RES,10.0K OHMS,1.0%,1/16W, 0402; AGILE_LINK: http://sj-agile9app/Agile/PLMServlet?action=OpenEmailObject&classid=10000&objid=146548997; Item Num: P02-11364R; LIFECYCLE_PHASE: Active; Lead Free Status: No; MFR_LIFECYCLE: Active; Manufacturer: Panasonic; Manufacturer Part Num: ERJ-2RKF1002X; Num Pins: 2; PART_SUBCLASS: RESISTORS; POWER: 1/16W; RESISTANCE: 10K; RoHS Compliant: Yes; TOLERANCE: +/-1%
R5-R9 = RESISTOR: RES 2.0K OHM 1/16W 1% 0402 SMD; Item Num: P02-16968R; Lead Free Status: Yes; Manufacturer: Vishay; Manufacturer Part Num: CRCW04022K00FKED; Num Pins: 2; Part Class: RESISTORS; Price: 0; RoHS Compliant: Yes
R11 = RESISTOR: RES,1.00K OHMS,1.0%,1/16W,0402; Item Num: P02-11372R; Lead Free Status: No; Manufacturer: Panasonic; Manufacturer Part Num: ERJ-2RKF1001X; Num Pins: 2; Part Class: Resistors
R12 = RESISTOR_0402: RES - 680 OHMS, 0402, 0.0632W, 1%, SMD; Item Num: P02-14154R; Lead Free Status: No; Manufacturer: Panasonic; Manufacturer Part Num: ERJ-S02F6800X; Num Pins: 2; Part Class: Resistors; Price: 0; RoHS Compliant: Yes
R13-R17 = RESISTOR: RES,4.70K OHMS,1.0%,1/16W,0402; AGILE_LINK: http://sj-agile9app/Agile/PLMServlet?action=OpenEmailObject&classid=10000&objid=146753272; Item Num: P02-11384R; LIFECYCLE_PHASE: Active; Lead Free Status: No; MFR_LIFECYCLE: Active; Manufacturer: Vishay; Manufacturer Part Num: CRCW04024K70FKED; Num Pins: 2; PART_SUBCLASS: RESISTORS; POWER: 1/16W; RESISTANCE: 4.7K; RoHS Compliant: Yes; TOLERANCE: +/-1%
R5295 R5296 = RESISTOR: RES ZERO OHM 1/16W 5% 0402 SMD; Altera Part No.: P02-14020R; Item Num: P02-14020R; Lead Free Status: No; Manufacturer: Panasonic; Manufacturer Part Num: ERJ-2GE0R00X; Num Pins: 2; Part Class: RESISTORS; Price: 0; RoHS Compliant: Yes; Tolerance: 5%
R5369 = RESISTOR: RES ZERO OHM 1/16W 5% 0402 SMD; Item Num: P02-14020R; Lead Free Status: No; Manufacturer: Panasonic; Manufacturer Part Num: ERJ-2GE0R00X; Num Pins: 2; Part Class: RESISTORS; RoHS Compliant: Yes
R5370 = RESISTOR: RES ZERO OHM 1/16W 5% 0402 SMD; Item Num: P02-14020R; Lead Free Status: No; Manufacturer: Panasonic; Manufacturer Part Num: ERJ-2GE0R00X; Num Pins: 2; Part Class: RESISTORS; Price: 0; RoHS Compliant: Yes
SW1 = SPDT_2: SWITCH SLIDE SPDT 2POS GULLWING; Item Num: P11-24549R; Manufacturer: Copal electronics Inc.; Manufacturer Part Num: CAS-D20TB1
U1 = 10SG280U_F2397B_v4_1.0
U2 = EPCQL_24TBGA: ICS - 1GBIT, MULTI-IO SERIAL NOR FLASH, 1.8V, TBGA-24 (6X8)MM; Item Num: P01-17829R; Lead Free Status: Yes; Manufacturer: Altera; Num Pins: 24; Part Class: ICs
V1 V2 = SENSE_PAD: Item Num: P23-SENSE; Manufacturer: NONE; Manufacturer Part Num: NONE

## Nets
1.8V: C2.1 C3.1 C832.1 R1.1 R2.1 R3.1 R4.1 R12.2 R13.2 R14.2 R15.2 R27.1 R30.1 R34.1 R5289.2 R5290.2 R5291.2 R5292.2 U2.B4(VCC) ; also on sheet 15 16 17 19 20 24 27 28 29 30 31 39 45
3.3V: C5.1 R28.2 R29.2 U3.1(ENABLE) U3.2(DISCEN) U3.12(VCC) ; also on sheet 17 18 19 23 24 25 27 28 29 30 32 34
GND: C1.2 C2.2 C3.2 C4.2 C5.2 C831.2 C832.2 D1.4(GND) D1.5(GND) R5.2 R6.2 R7.2 R8.2 R9.2 R11.2 R16.1 R17.1 R18.1 R19.1 R20.1 R22.1 R24.2 U1.AP24(VSIGN_1) U1.AR24(VSIGP_1) U1.AT24(VSIGN_0) U1.AU24(VSIGP_0) U2.B3(VSS) U3.5(ACCn) U3.6(GND) U3.11(VCC2) U84.5(ACCn) U84.6(GND) U84.11(VCC2) V2.2(SNS) ; also on sheet 10 11 12 13 14 15 16 17 18 19 20 21 23 24 25 27 28 29 30 31 32 33 34 35 36 37 38 39 40 41 42 43 44 45 46
VCC_ALERTn: U1.BB24(SDM_IO12,_PWRMGT_PWM0,_PWRMGT_SDA,_NAND_WP_N) ; also on sheet 35
VCC_PWM: R5369.2 R5370.2 U1.BD23(SDM_IO0,INIT_DONE,PWRMGT_PWM0,PWRMGT_SCL)
VCCIO3V: D46.1(K) ; also on sheet 15 31 44 45 46
A10_VREF_ADC_N: U1.AP23(VREFN_ADC) V2.1(RSNS)
A10_VREF_ADC_P: U1.AR23(VREFP_ADC) V1.1(RSNS)
CLK_ENET_N: R5298.1 U1.AN28(IO,_CLK_2F_1N,_LVDS2F_12N,_DQ33) ; also on sheet 18
CLK_ENET_P: R5298.2 U1.AN27(IO,_CLK_2F_1P,_LVDS2F_12P,_DQ33) ; also on sheet 18
CLK_FPGA_50M: U1.BH33(IO,_CLK_2B_1P,_LVDS2B_12P,_DQ41) ; also on sheet 18
CLK_HILO_N: R23.2 U1.N35(IO,_CLK_2M_1N,_LVDS2M_12N,_DQ5) ; also on sheet 18
CLK_HILO_P: R23.1 U1.M35(IO,_CLK_2M_1P,_LVDS2M_12P,_DQ5) ; also on sheet 18
DP_AUX_CH_N: U1.AN25(IO,_LVDS2F_8N,_DQ33) ; also on sheet 24
DP_AUX_CH_P: U1.AP25(IO,_LVDS2F_8P,_DQ33) ; also on sheet 24
DP_AUX_TX_DRV_IN: U1.AY26(IO,_LVDS2F_6N,_DQ32) ; also on sheet 24
DP_AUX_TX_DRV_OE: U1.AW26(IO,_LVDS2F_6P,_DQ32) ; also on sheet 24
DP_AUX_TX_DRV_OUT: U1.AT27(IO,_LVDS2F_5P,_DQ32) ; also on sheet 24
DP_CONFIG1: U1.AN26(IO,_LVDS2F_7N,_DQ33) ; also on sheet 24
DP_CONFIG2: U1.AP26(IO,_LVDS2F_7P,_DQ33) ; also on sheet 24
DP_HOT_PLUG: U1.AU27(IO,_LVDS2F_5N,_DQ32) ; also on sheet 24
ENET_INTn: U1.AC35(IO3V2_12) ; also on sheet 21
ENET_MDC: U1.AD35(IO3V1_12) ; also on sheet 21
ENET_MDIO: U1.AD34(IO3V0_12,_NPERSTL2) ; also on sheet 21
ENET_RESETn: U1.AB34(IO3V3_12) ; also on sheet 21
ENET_RX_N: U1.AW25(IO,_LVDS2F_2N,_DQ32) ; also on sheet 21
ENET_RX_P: U1.AV25(IO,_LVDS2F_2P,_DQ32) ; also on sheet 21
ENET_TX_N: U1.AT25(IO,_LVDS2F_1N,_DQ32) ; also on sheet 21
ENET_TX_P: U1.AU25(IO,_LVDS2F_1P,_DQ32) ; also on sheet 21
FLASH_ADDR1: U1.AU28(IO,_LVDS2A_1N,_DQ44) ; also on sheet 19 20
FLASH_ADDR2: U1.AU29(IO,_LVDS2A_1P,_DQ44) ; also on sheet 19 20
FLASH_ADDR3: U1.AW29(IO,_LVDS2A_2N,_DQ44) ; also on sheet 19 20
FLASH_ADDR4: U1.AY29(IO,_LVDS2A_2P,_DQ44) ; also on sheet 19 20
FLASH_ADDR5: U1.BB28(IO,_LVDS2A_3N,_DQ44) ; also on sheet 19 20
FLASH_ADDR6: U1.BA29(IO,_LVDS2A_3P,_DQ44) ; also on sheet 19 20
FLASH_ADDR7: U1.AV28(IO,_LVDS2A_4N,_DQSN44) ; also on sheet 19 20
FLASH_ADDR8: U1.AW28(IO,_LVDS2A_4P,_DQS44) ; also on sheet 19 20
FLASH_ADDR9: U1.AV30(IO,_LVDS2A_5N,_DQ44) ; also on sheet 19 20
FLASH_ADDR10: U1.AU30(IO,_LVDS2A_5P,_DQ44) ; also on sheet 19 20
FLASH_ADDR11: U1.AT30(IO,_LVDS2A_6N,_DQ44) ; also on sheet 19 20
FLASH_ADDR12: U1.AT29(IO,_LVDS2A_6P,_DQ44) ; also on sheet 19 20
FLASH_ADDR13: U1.BA30(IO,_LVDS2A_7N,_DQ45) ; also on sheet 19 20
FLASH_ADDR14: U1.BA31(IO,_LVDS2A_7P,_DQ45) ; also on sheet 19 20
FLASH_ADDR15: U1.BB29(IO,_LVDS2A_8N,_DQ45) ; also on sheet 19 20
FLASH_ADDR16: U1.BB30(IO,_LVDS2A_8P,_DQ45) ; also on sheet 19 20
FLASH_ADDR17: U1.BC32(IO,_LVDS2A_9N,_DQ45) ; also on sheet 19 20
FLASH_ADDR18: U1.BC31(IO,_LVDS2A_9P,_DQ45) ; also on sheet 19 20
FLASH_ADDR19: U1.BB32(IO,_PLL_2A_CLKOUT1N,_LVDS2A_10N,_DQSN45) ; also on sheet 19 20
FLASH_ADDR20: U1.BA32(IO,_PLL_2A_CLKOUT1P,_PLL_2A_CLKOUT1,_PLL_2A_FBN,_LVDS2A_10P,_DQS45) ; also on sheet 19 20
FLASH_ADDR21: U1.AY32(IO,_LVDS2A_11N,_DQ45) ; also on sheet 19 20
FLASH_ADDR22: U1.BD30(IO,_LVDS2A_16N,_DQSN46) ; also on sheet 19 20
FLASH_ADDR23: U1.BC30(IO,_LVDS2A_16P,_DQS46) ; also on sheet 19 20
FLASH_ADDR24: U1.BG28(IO,_LVDS2A_17N,_DQ46) ; also on sheet 19 20
FLASH_ADDR25: U1.BG29(IO,_LVDS2A_17P,_DQ46) ; also on sheet 19 20
FLASH_ADDR26: U1.BH30(IO,_LVDS2A_18N,_DQ46) ; also on sheet 19 20
FLASH_ADVn: U1.BE28(IO,_LVDS2A_19N,_DQ47) ; also on sheet 19 20
FLASH_CEn0: U1.BJ29(IO,_LVDS2A_20N,_DQ47) ; also on sheet 19 20
FLASH_CEn1: U1.BJ31(IO,_LVDS2A_22N,_DQSN47) ; also on sheet 19 20
FLASH_CLK: U1.BF31(IO,_PLL_2A_CLKOUT0P,_PLL_2A_CLKOUT0,_PLL_2A_FBP,_PLL_2A_FB0,_LVDS2A_15P,_DQ46) ; also on sheet 19 20
FLASH_DATA0: U1.BD36(IO,_LVDS2B_1N,_DQ40) ; also on sheet 19 20
FLASH_DATA1: U1.BE36(IO,_LVDS2B_1P,_DQ40) ; also on sheet 19 20
FLASH_DATA2: U1.BC35(IO,_LVDS2B_2N,_DQ40) ; also on sheet 19 20
FLASH_DATA3: U1.BC36(IO,_LVDS2B_2P,_DQ40) ; also on sheet 19 20
FLASH_DATA4: U1.BB34(IO,_LVDS2B_3N,_DQ40) ; also on sheet 19 20
FLASH_DATA5: U1.BB33(IO,_LVDS2B_3P,_DQ40) ; also on sheet 19 20
FLASH_DATA6: U1.BD35(IO,_LVDS2B_4N,_DQSN40) ; also on sheet 19 20
FLASH_DATA7: U1.BD34(IO,_LVDS2B_4P,_DQS40) ; also on sheet 19 20
FLASH_DATA8: U1.BC33(IO,_LVDS2B_5N,_DQ40) ; also on sheet 19 20
FLASH_DATA9: U1.BD33(IO,_LVDS2B_5P,_DQ40) ; also on sheet 19 20
FLASH_DATA10: U1.BF35(IO,_LVDS2B_6N,_DQ40) ; also on sheet 19 20
FLASH_DATA11: U1.BF36(IO,_LVDS2B_6P,_DQ40) ; also on sheet 19 20
FLASH_DATA12: U1.BF34(IO,_LVDS2B_7N,_DQ41) ; also on sheet 19 20
FLASH_DATA13: U1.BG34(IO,_LVDS2B_7P,_DQ41) ; also on sheet 19 20
FLASH_DATA14: U1.BJ34(IO,_LVDS2B_8N,_DQ41) ; also on sheet 19 20
FLASH_DATA15: U1.BJ33(IO,_LVDS2B_8P,_DQ41) ; also on sheet 19 20
FLASH_OEn: U1.BJ30(IO,_LVDS2A_20P,_DQ47) ; also on sheet 19 20
FLASH_RDYBSYn0: U1.BF29(IO,_LVDS2A_19P,_DQ47) ; also on sheet 19 20
FLASH_RDYBSYn1: U1.BJ28(IO,_LVDS2A_21P,_DQ47) ; also on sheet 19 20
FLASH_RESETn: U1.BG30(IO,_LVDS2A_18P,_DQ46) ; also on sheet 19 20
FLASH_WEn: U1.BH28(IO,_LVDS2A_21N,_DQ47) ; also on sheet 19 20
FMCA_3P3V_SCL: R29.1 U3.4(SCLIN) ; also on sheet 25
FMCA_3P3V_SDA: R28.1 U3.9(SDAIN) ; also on sheet 25
FMCA_CLK_M2C_N0: U1.AT17(IO,_CLK_3B_1P,_LVDS3B_12P,_DQ89) ; also on sheet 25
FMCA_CLK_M2C_N1: U1.AR19(IO,_CLK_3C_1P,_LVDS3C_12P,_DQ85) ; also on sheet 25
FMCA_CLK_M2C_P0: U1.AU17(IO,_CLK_3B_1N,_LVDS3B_12N,_DQ89) ; also on sheet 25
FMCA_CLK_M2C_P1: U1.AT19(IO,_CLK_3C_1N,_LVDS3C_12N,_DQ85) ; also on sheet 25
FMCA_GA0: U1.BJ20(IO,_LVDS3C_22N,_DQSN87) ; also on sheet 25
FMCA_GA1: U1.BJ19(IO,_LVDS3C_22P,_DQS87) ; also on sheet 25
FMCA_LA_RX_CLK_N0: U1.AV10(IO,_CLK_3B_0N,_LVDS3B_13N,_DQ90) ; also on sheet 25
FMCA_LA_RX_CLK_N1: U1.BE21(IO,_CLK_3C_0N,_LVDS3C_13N,_DQ86) ; also on sheet 25
FMCA_LA_RX_CLK_P0: U1.AW10(IO,_CLK_3B_0P,_LVDS3B_13P,_DQ90) ; also on sheet 25
FMCA_LA_RX_CLK_P1: U1.BF21(IO,_CLK_3C_0P,_LVDS3C_13P,_DQ86) ; also on sheet 25
FMCA_LA_RX_N0: U1.AN18(IO,_LVDS3B_11N,_DQ89) ; also on sheet 25
FMCA_LA_RX_N1: U1.AR21(IO,_LVDS3C_7N,_DQ85) ; also on sheet 25
FMCA_LA_RX_N2: U1.AR18(IO,_LVDS3B_7N,_DQ89) ; also on sheet 25
FMCA_LA_RX_N3: U1.AP20(IO,_LVDS3C_9N,_DQ85) ; also on sheet 25
FMCA_LA_RX_N4: U1.AP16(IO,_LVDS3B_1N,_DQ88) ; also on sheet 25
FMCA_LA_RX_N5: U1.BA19(IO,_LVDS3C_6N,_DQ84) ; also on sheet 25
FMCA_LA_RX_N6: U1.AR16(IO,_PLL_3B_CLKOUT1N,_LVDS3B_10N,_DQSN89) ; also on sheet 25
FMCA_LA_RX_N7: U1.BF19(IO,_LVDS3C_16N,_DQSN86) ; also on sheet 25
FMCA_LA_RX_N8: U1.AT16(IO,_LVDS3B_9N,_DQ89) ; also on sheet 25
FMCA_LA_RX_N9: U1.AT14(IO,_LVDS3B_6N,_DQ88) ; also on sheet 25
FMCA_LA_RX_N10: U1.AU14(IO,_LVDS3B_8N,_DQ89) ; also on sheet 25
FMCA_LA_RX_N11: U1.BJ18(IO,_LVDS3C_24N,_DQ87) ; also on sheet 25
FMCA_LA_RX_N12: U1.AU13(IO,_LVDS3B_2N,_DQ88) ; also on sheet 25
FMCA_LA_RX_N13: U1.AY13(IO,_LVDS3B_14N,_DQ90) ; also on sheet 25
FMCA_LA_RX_N14: U1.BE11(IO,_LVDS3B_22N,_DQSN91) ; also on sheet 25
FMCA_LA_RX_P0: U1.AN17(IO,_RZQ_3B,_LVDS3B_11P,_DQ89) ; also on sheet 25
FMCA_LA_RX_P1: U1.AT21(IO,_LVDS3C_7P,_DQ85) ; also on sheet 25
FMCA_LA_RX_P2: U1.AP18(IO,_LVDS3B_7P,_DQ89) ; also on sheet 25
FMCA_LA_RX_P3: U1.AN20(IO,_LVDS3C_9P,_DQ85) ; also on sheet 25
FMCA_LA_RX_P4: U1.AP15(IO,_LVDS3B_1P,_DQ88) ; also on sheet 25
FMCA_LA_RX_P5: U1.BB19(IO,_LVDS3C_6P,_DQ84) ; also on sheet 25
FMCA_LA_RX_P6: U1.AR17(IO,_PLL_3B_CLKOUT1P,_PLL_3B_CLKOUT1,_PLL_3B_FBN,_LVDS3B_10P,_DQS89) ; also on sheet 25
FMCA_LA_RX_P7: U1.BE19(IO,_LVDS3C_16P,_DQS86) ; also on sheet 25
FMCA_LA_RX_P8: U1.AT15(IO,_LVDS3B_9P,_DQ89) ; also on sheet 25
FMCA_LA_RX_P9: U1.AR14(IO,_LVDS3B_6P,_DQ88) ; also on sheet 25
FMCA_LA_RX_P10: U1.AU15(IO,_LVDS3B_8P,_DQ89) ; also on sheet 25
FMCA_LA_RX_P11: U1.BH18(IO,_LVDS3C_24P,_DQ87) ; also on sheet 25
FMCA_LA_RX_P12: U1.AV13(IO,_LVDS3B_2P,_DQ88) ; also on sheet 25
FMCA_LA_RX_P13: U1.AW13(IO,_LVDS3B_14P,_DQ90) ; also on sheet 25
FMCA_LA_RX_P14: U1.BE12(IO,_LVDS3B_22P,_DQS91) ; also on sheet 25
FMCA_LA_TX_N0: U1.AP14(IO,_LVDS3B_5N,_DQ88) ; also on sheet 25
FMCA_LA_TX_N1: U1.AU12(IO,_LVDS3B_3N,_DQ88) ; also on sheet 25
FMCA_LA_TX_N2: U1.AU20(IO,_LVDS3C_8N,_DQ85) ; also on sheet 25
FMCA_LA_TX_N3: U1.AV12(IO,_PLL_3B_CLKOUT0N,_LVDS3B_15N,_DQ90) ; also on sheet 25
FMCA_LA_TX_N4: U1.AW20(IO,_LVDS3C_5N,_DQ84) ; also on sheet 25
FMCA_LA_TX_N5: U1.AW11(IO,_LVDS3B_18N,_DQ90) ; also on sheet 25
FMCA_LA_TX_N6: U1.BB18(IO,_LVDS3C_17N,_DQ86) ; also on sheet 25
FMCA_LA_TX_N7: U1.AY12(IO,_LVDS3B_16N,_DQSN90) ; also on sheet 25
FMCA_LA_TX_N8: U1.BD18(IO,_LVDS3C_18N,_DQ86) ; also on sheet 25
FMCA_LA_TX_N9: U1.BA11(IO,_LVDS3B_17N,_DQ90) ; also on sheet 25
FMCA_LA_TX_N10: U1.BB12(IO,_LVDS3B_20N,_DQ91) ; also on sheet 25
FMCA_LA_TX_N11: U1.BF17(IO,_LVDS3C_23N,_DQ87) ; also on sheet 25
FMCA_LA_TX_N12: U1.BB10(IO,_LVDS3B_21N,_DQ91) ; also on sheet 25
FMCA_LA_TX_N13: U1.BH17(IO,_LVDS3C_21N,_DQ87) ; also on sheet 25
FMCA_LA_TX_N14: U1.BC11(IO,_LVDS3B_19N,_DQ91) ; also on sheet 25
FMCA_LA_TX_N15: U1.BD10(IO,_LVDS3B_23N,_DQ91) ; also on sheet 25
FMCA_LA_TX_N16: U1.BF10(IO,_LVDS3B_24N,_DQ91) ; also on sheet 25
FMCA_LA_TX_P0: U1.AP13(IO,_LVDS3B_5P,_DQ88) ; also on sheet 25
FMCA_LA_TX_P1: U1.AT12(IO,_LVDS3B_3P,_DQ88) ; also on sheet 25
FMCA_LA_TX_P2: U1.AT20(IO,_LVDS3C_8P,_DQ85) ; also on sheet 25
FMCA_LA_TX_P3: U1.AV11(IO,_PLL_3B_CLKOUT0P,_PLL_3B_CLKOUT0,_PLL_3B_FBP,_PLL_3B_FB0,_LVDS3B_15P,_DQ90) ; also on sheet 25
FMCA_LA_TX_P4: U1.AW19(IO,_LVDS3C_5P,_DQ84) ; also on sheet 25
FMCA_LA_TX_P5: U1.AY11(IO,_LVDS3B_18P,_DQ90) ; also on sheet 25
FMCA_LA_TX_P6: U1.BC18(IO,_LVDS3C_17P,_DQ86) ; also on sheet 25
FMCA_LA_TX_P7: U1.BA12(IO,_LVDS3B_16P,_DQS90) ; also on sheet 25
FMCA_LA_TX_P8: U1.BE18(IO,_LVDS3C_18P,_DQ86) ; also on sheet 25
FMCA_LA_TX_P9: U1.BA10(IO,_LVDS3B_17P,_DQ90) ; also on sheet 25
FMCA_LA_TX_P10: U1.BC12(IO,_LVDS3B_20P,_DQ91) ; also on sheet 25
FMCA_LA_TX_P11: U1.BE17(IO,_LVDS3C_23P,_DQ87) ; also on sheet 25
FMCA_LA_TX_P12: U1.BC10(IO,_LVDS3B_21P,_DQ91) ; also on sheet 25
FMCA_LA_TX_P13: U1.BG17(IO,_LVDS3C_21P,_DQ87) ; also on sheet 25
FMCA_LA_TX_P14: U1.BD11(IO,_LVDS3B_19P,_DQ91) ; also on sheet 25
FMCA_LA_TX_P15: U1.BE10(IO,_LVDS3B_23P,_DQ91) ; also on sheet 25
FMCA_LA_TX_P16: U1.BF11(IO,_LVDS3B_24P,_DQ91) ; also on sheet 25
FMCA_SCL: R26.1 U1.BH21(IO,_LVDS3C_20N,_DQ87) U3.3(SCLOUT)
FMCA_SDA: R25.1 U1.BH20(IO,_LVDS3C_20P,_DQ87) U3.10(SDAOUT)
FPGA_AVST_CLK: U1.AY19(IO,_LVDS3A_24P,_DQ95,_AVST_CLK) ; also on sheet 19
FPGA_AVST_READY: U1.BE24(SDM_IO8,_AVST_READY,_AS_NCSO3) ; also on sheet 19
FPGA_AVST_VALID: U1.BH13(IO,_RZQ_3A,_LVDS3A_11P,_DQ93,_AVST_VALID) ; also on sheet 19
FPGA_CONF_DONE: U1.BG23(SDM_IO16,_CONF_DONE,_PWRMGT_SDA) ; also on sheet 19
FPGA_CONFIG_D0: U1.BD13(IO,_LVDS3A_1N,_DQ92,_AVST_DATA0) ; also on sheet 19
FPGA_CONFIG_D1: U1.BE13(IO,_LVDS3A_1P,_DQ92,_AVST_DATA1) ; also on sheet 19
FPGA_CONFIG_D2: U1.BF15(IO,_LVDS3A_2N,_DQ92,_AVST_DATA2) ; also on sheet 19
FPGA_CONFIG_D3: U1.BG15(IO,_LVDS3A_2P,_DQ92,_AVST_DATA3) ; also on sheet 19
FPGA_CONFIG_D4: U1.BE14(IO,_LVDS3A_3N,_DQ92,_AVST_DATA4) ; also on sheet 19
FPGA_CONFIG_D5: U1.BF14(IO,_LVDS3A_3P,_DQ92,_AVST_DATA5) ; also on sheet 19
FPGA_CONFIG_D6: U1.BE16(IO,_LVDS3A_4N,_DQSN92,_AVST_DATA6) ; also on sheet 19
FPGA_CONFIG_D7: U1.BF16(IO,_LVDS3A_4P,_DQS92,_AVST_DATA7) ; also on sheet 19
FPGA_CONFIG_D8: U1.BD16(IO,_LVDS3A_5N,_DQ92,_AVST_DATA8) ; also on sheet 19
FPGA_CONFIG_D9: U1.BC16(IO,_LVDS3A_5P,_DQ92,_AVST_DATA9) ; also on sheet 19
FPGA_CONFIG_D10: U1.BD14(IO,_LVDS3A_6N,_DQ92,_AVST_DATA10) ; also on sheet 19
FPGA_CONFIG_D11: U1.BD15(IO,_LVDS3A_6P,_DQ92,_AVST_DATA11) ; also on sheet 19
FPGA_CONFIG_D12: U1.BF12(IO,_LVDS3A_7N,_DQ93,_AVST_DATA12) ; also on sheet 19
FPGA_CONFIG_D13: U1.BG12(IO,_LVDS3A_7P,_DQ93,_AVST_DATA13) ; also on sheet 19
FPGA_CONFIG_D14: U1.BJ13(IO,_LVDS3A_8N,_DQ93,_AVST_DATA14) ; also on sheet 19
FPGA_CONFIG_D15: U1.BJ14(IO,_LVDS3A_8P,_DQ93,_AVST_DATA15) ; also on sheet 19
FPGA_CvP_CONFDONE: R27.2 U1.BD25(SDM_IO15,_AVSTX8_DATA6,_SDMMC_CFG_DATA6,_NAND_ADQ4) ; also on sheet 19
FPGA_INIT_DONE: R5369.1 ; also on sheet 19
FPGA_nCONFIG: R1.2 U1.AY22(NCONFIG) ; also on sheet 19
FPGA_nSTATUS: R2.2 U1.BJ21(NSTATUS) ; also on sheet 19
FPGA_OSC_CLK1: U1.BA22(OSC_CLK_1) ; also on sheet 18
FPGA_PR_DONE: R30.2 U1.BA17(IO,_LVDS3A_20N,_DQ95) ; also on sheet 19
FPGA_PR_ERROR: R34.2 U1.AY16(IO,_LVDS3A_21N,_DQ95) ; also on sheet 19
FPGA_PR_REQUEST: U1.BC13(IO,_LVDS3A_18P,_DQ94) ; also on sheet 19
LT_1.8V_SCL: R5292.1 R5296.2 U1.BG22(SDM_IO14,_AVSTX8_CLK,_PWRMGT_SCL,_NAND_ADQ7) U84.3(SCLOUT)
LT_1.8V_SDA: R5291.1 R5295.2 U1.BF22(SDM_IO11,_AVSTX8_VALID,_PWRMGT_SDA,_NAND_ADQ6) U84.10(SDAOUT)
LT_IO_SCL: R5296.1 ; also on sheet 10
LT_IO_SDA: R5295.1 ; also on sheet 10
LT_SCL: U84.4(SCLIN) ; also on sheet 31 35
LT_SDA: U84.9(SDAIN) ; also on sheet 31 35
MAX5_BEn0: U1.AY36(IO,_LVDS2B_17N,_DQ42) ; also on sheet 19
MAX5_BEn1: U1.BA36(IO,_LVDS2B_17P,_DQ42) ; also on sheet 19
MAX5_BEn2: U1.BA34(IO,_LVDS2B_18N,_DQ42) ; also on sheet 19
MAX5_BEn3: U1.AY34(IO,_LVDS2B_18P,_DQ42) ; also on sheet 19
MAX5_CLK: R21.2 ; also on sheet 19
MAX5_CSn: U1.AV33(IO,_LVDS2B_20P,_DQ43) ; also on sheet 19
MAX5_OEn: U1.AV32(IO,_LVDS2B_20N,_DQ43) ; also on sheet 19
MAX5_WEn: U1.AT34(IO,_LVDS2B_21N,_DQ43) ; also on sheet 19
MEM_ADDR_CMD0: U1.K38(IO,_LVDS2M_18P,_DQ6) ; also on sheet 23
MEM_ADDR_CMD1: U1.L37(IO,_LVDS2M_18N,_DQ6) ; also on sheet 23
MEM_ADDR_CMD2: U1.M37(IO,_LVDS2M_17P,_DQ6) ; also on sheet 23
MEM_ADDR_CMD3: U1.M38(IO,_LVDS2M_17N,_DQ6) ; also on sheet 23
MEM_ADDR_CMD4: U1.J39(IO,_LVDS2M_16P,_DQS6) ; also on sheet 23
MEM_ADDR_CMD5: U1.J38(IO,_LVDS2M_16N,_DQSN6) ; also on sheet 23
MEM_ADDR_CMD6: U1.K39(IO,_PLL_2M_CLKOUT0P,_PLL_2M_CLKOUT0,_PLL_2M_FBP,_PLL_2M_FB0,_LVDS2M_15P,_DQ6) ; also on sheet 23
MEM_ADDR_CMD7: U1.L39(IO,_PLL_2M_CLKOUT0N,_LVDS2M_15N,_DQ6) ; also on sheet 23
MEM_ADDR_CMD8: U1.P37(IO,_LVDS2M_14P,_DQ6) ; also on sheet 23
MEM_ADDR_CMD9: U1.R37(IO,_LVDS2M_14N,_DQ6) ; also on sheet 23
MEM_ADDR_CMD10: U1.N37(IO,_CLK_2M_0P,_LVDS2M_13P,_DQ6) ; also on sheet 23
MEM_ADDR_CMD11: U1.P38(IO,_CLK_2M_0N,_LVDS2M_13N,_DQ6) ; also on sheet 23
MEM_ADDR_CMD12: U1.P35(IO,_LVDS2M_11N,_DQ5) ; also on sheet 23
MEM_ADDR_CMD13: U1.K36(IO,_PLL_2M_CLKOUT1P,_PLL_2M_CLKOUT1,_PLL_2M_FBN,_LVDS2M_10P,_DQS5) ; also on sheet 23
MEM_ADDR_CMD14: U1.K37(IO,_PLL_2M_CLKOUT1N,_LVDS2M_10N,_DQSN5) ; also on sheet 23
MEM_ADDR_CMD15: U1.N36(IO,_LVDS2M_9P,_DQ5) ; also on sheet 23
MEM_ADDR_CMD16: U1.L36(IO,_LVDS2M_8N,_DQ5) ; also on sheet 23
MEM_ADDR_CMD17: U1.T35(IO,_LVDS2M_7P,_DQ5) ; also on sheet 23
MEM_ADDR_CMD18: U1.R36(IO,_LVDS2M_7N,_DQ5) ; also on sheet 23
MEM_ADDR_CMD19: U1.L35(IO,_LVDS2M_8P,_DQ5) ; also on sheet 23
MEM_ADDR_CMD20: U1.L40(IO,_LVDS2M_21P,_DQ7) ; also on sheet 23
MEM_ADDR_CMD21: U1.K40(IO,_LVDS2M_21N,_DQ7) ; also on sheet 23
MEM_ADDR_CMD22: U1.G38(IO,_LVDS2M_23P,_DQ7) ; also on sheet 23
MEM_ADDR_CMD23: U1.H38(IO,_LVDS2M_23N,_DQ7) ; also on sheet 23
MEM_ADDR_CMD24: U1.G40(IO,_LVDS2M_22P,_DQS7) ; also on sheet 23
MEM_ADDR_CMD25: U1.F40(IO,_LVDS2M_22N,_DQSN7) ; also on sheet 23
MEM_ADDR_CMD26: U1.P36(IO,_LVDS2M_9N,_DQ5) ; also on sheet 23
MEM_ADDR_CMD27: U1.E40(IO,_LVDS2M_24N,_DQ7) ; also on sheet 23
MEM_ADDR_CMD28: U1.D40(IO,_LVDS2M_24P,_DQ7) ; also on sheet 23
MEM_ADDR_CMD29: U1.R33(IO,_LVDS2M_6P,_DQ4) ; also on sheet 23
MEM_ADDR_CMD30: U1.J40(IO,_LVDS2M_19P,_DQ7) ; also on sheet 23
MEM_ADDR_CMD31: U1.H40(IO,_LVDS2M_19N,_DQ7) ; also on sheet 23
MEM_CLK_N: U1.G39(IO,_LVDS2M_20N,_DQ7) ; also on sheet 23
MEM_CLK_P: U1.F39(IO,_LVDS2M_20P,_DQ7) ; also on sheet 23
MEM_DMA0: U1.E27(IO,_LVDS2L_1N,_DQ8) ; also on sheet 23
MEM_DMA1: U1.M27(IO,_LVDS2L_8N,_DQ9) ; also on sheet 23
MEM_DMA2: U1.V30(IO,_CLK_2L_0N,_LVDS2L_13N,_DQ10) ; also on sheet 23
MEM_DMA3: U1.P25(IO,_LVDS2L_19P,_DQ11) ; also on sheet 23
MEM_DMB0: U1.K32(IO,_LVDS2N_3P,_DQ0) ; also on sheet 23
MEM_DMB1: U1.J33(IO,_CLK_2N_1P,_LVDS2N_12P,_DQ1) ; also on sheet 23
MEM_DMB2: U1.F37(IO,_LVDS2N_17N,_DQ2) ; also on sheet 23
MEM_DMB3: U1.C36(IO,_LVDS2N_19N,_DQ3) ; also on sheet 23
MEM_DQ_ADDR_CMD0: U1.T31(IO,_LVDS2M_2N,_DQ4) ; also on sheet 23
MEM_DQ_ADDR_CMD1: U1.R34(IO,_LVDS2M_3P,_DQ4) ; also on sheet 23
MEM_DQ_ADDR_CMD2: U1.R31(IO,_LVDS2M_2P,_DQ4) ; also on sheet 23
MEM_DQ_ADDR_CMD3: U1.U33(IO,_LVDS2M_1P,_DQ4) ; also on sheet 23
MEM_DQ_ADDR_CMD4: U1.U34(IO,_LVDS2M_1N,_DQ4) ; also on sheet 23
MEM_DQ_ADDR_CMD5: U1.T34(IO,_LVDS2M_3N,_DQ4) ; also on sheet 23
MEM_DQ_ADDR_CMD6: U1.U32(IO,_LVDS2M_5N,_DQ4) ; also on sheet 23
MEM_DQ_ADDR_CMD7: U1.V32(IO,_LVDS2M_5P,_DQ4) ; also on sheet 23
MEM_DQ_ADDR_CMD8: U1.P33(IO,_LVDS2M_6N,_DQ4) ; also on sheet 23
MEM_DQA0: U1.B27(IO,_LVDS2L_3P,_DQ8) ; also on sheet 23
MEM_DQA1: U1.F27(IO,_LVDS2L_2P,_DQ8) ; also on sheet 23
MEM_DQA2: U1.G27(IO,_LVDS2L_2N,_DQ8) ; also on sheet 23
MEM_DQA3: U1.C27(IO,_LVDS2L_3N,_DQ8) ; also on sheet 23
MEM_DQA4: U1.C26(IO,_LVDS2L_5P,_DQ8) ; also on sheet 23
MEM_DQA5: U1.B25(IO,_LVDS2L_5N,_DQ8) ; also on sheet 23
MEM_DQA6: U1.D26(IO,_LVDS2L_1P,_DQ8) ; also on sheet 23
MEM_DQA7: U1.D25(IO,_LVDS2L_6N,_DQ8) ; also on sheet 23
MEM_DQA8: U1.H27(IO,_LVDS2L_9N,_DQ9) ; also on sheet 23
MEM_DQA9: U1.H26(IO,_LVDS2L_9P,_DQ9) ; also on sheet 23
MEM_DQA10: U1.J25(IO,_CLK_2L_1P,_LVDS2L_12P,_DQ9) ; also on sheet 23
MEM_DQA11: U1.H25(IO,_CLK_2L_1N,_LVDS2L_12N,_DQ9) ; also on sheet 23
MEM_DQA12: U1.L27(IO,_LVDS2L_8P,_DQ9) ; also on sheet 23
MEM_DQA13: U1.L26(IO,_LVDS2L_7N,_DQ9) ; also on sheet 23
MEM_DQA14: U1.G25(IO,_LVDS2L_11N,_DQ9) ; also on sheet 23
MEM_DQA15: U1.K27(IO,_LVDS2L_7P,_DQ9) ; also on sheet 23
MEM_DQA16: U1.U29(IO,_PLL_2L_CLKOUT0P,_PLL_2L_CLKOUT0,_PLL_2L_FBP,_PLL_2L_FB0,_LVDS2L_15P,_DQ10) ; also on sheet 23
MEM_DQA17: U1.T30(IO,_LVDS2L_14N,_DQ10) ; also on sheet 23
MEM_DQA18: U1.T29(IO,_LVDS2L_14P,_DQ10) ; also on sheet 23
MEM_DQA19: U1.V26(IO,_LVDS2L_17N,_DQ10) ; also on sheet 23
MEM_DQA20: U1.U30(IO,_CLK_2L_0P,_LVDS2L_13P,_DQ10) ; also on sheet 23
MEM_DQA21: U1.V25(IO,_LVDS2L_17P,_DQ10) ; also on sheet 23
MEM_DQA22: U1.U28(IO,_PLL_2L_CLKOUT0N,_LVDS2L_15N,_DQ10) ; also on sheet 23
MEM_DQA23: U1.U27(IO,_LVDS2L_18N,_DQ10) ; also on sheet 23
MEM_DQA24: U1.T25(IO,_LVDS2L_21N,_DQ11) ; also on sheet 23
MEM_DQA25: U1.N27(IO,_LVDS2L_24N,_DQ11) ; also on sheet 23
MEM_DQA26: U1.L25(IO,_LVDS2L_23P,_DQ11) ; also on sheet 23
MEM_DQA27: U1.U25(IO,_LVDS2L_21P,_DQ11) ; also on sheet 23
MEM_DQA28: U1.N26(IO,_LVDS2L_24P,_DQ11) ; also on sheet 23
MEM_DQA29: U1.R26(IO,_LVDS2L_20P,_DQ11) ; also on sheet 23
MEM_DQA30: U1.P26(IO,_LVDS2L_20N,_DQ11) ; also on sheet 23
MEM_DQA31: U1.N25(IO,_LVDS2L_19N,_DQ11) ; also on sheet 23
MEM_DQA32: U1.F25(IO,_RZQ_2L,_LVDS2L_11P,_DQ9) ; also on sheet 23
MEM_DQA33: U1.M25(IO,_LVDS2L_23N,_DQ11) ; also on sheet 23
MEM_DQB0: U1.K34(IO,_LVDS2N_1P,_DQ0) ; also on sheet 23
MEM_DQB1: U1.K33(IO,_LVDS2N_3N,_DQ0) ; also on sheet 23
MEM_DQB2: U1.N33(IO,_LVDS2N_5N,_DQ0) ; also on sheet 23
MEM_DQB3: U1.M33(IO,_LVDS2N_5P,_DQ0) ; also on sheet 23
MEM_DQB4: U1.J34(IO,_LVDS2N_1N,_DQ0) ; also on sheet 23
MEM_DQB5: U1.N32(IO,_LVDS2N_2N,_DQ0) ; also on sheet 23
MEM_DQB6: U1.N31(IO,_LVDS2N_2P,_DQ0) ; also on sheet 23
MEM_DQB7: U1.M34(IO,_LVDS2N_6N,_DQ0) ; also on sheet 23
MEM_DQB8: U1.E34(IO,_LVDS2N_7P,_DQ1) ; also on sheet 23
MEM_DQB9: U1.F34(IO,_LVDS2N_7N,_DQ1) ; also on sheet 23
MEM_DQB10: U1.H35(IO,_LVDS2N_8P,_DQ1) ; also on sheet 23
MEM_DQB11: U1.J35(IO,_LVDS2N_8N,_DQ1) ; also on sheet 23
MEM_DQB12: U1.G35(IO,_LVDS2N_9P,_DQ1) ; also on sheet 23
MEM_DQB13: U1.H36(IO,_LVDS2N_11N,_DQ1) ; also on sheet 23
MEM_DQB14: U1.F35(IO,_LVDS2N_9N,_DQ1) ; also on sheet 23
MEM_DQB15: U1.H33(IO,_CLK_2N_1N,_LVDS2N_12N,_DQ1) ; also on sheet 23
MEM_DQB16: U1.D34(IO,_PLL_2N_CLKOUT0P,_PLL_2N_CLKOUT0,_PLL_2N_FBP,_PLL_2N_FB0,_LVDS2N_15P,_DQ2) ; also on sheet 23
MEM_DQB17: U1.E38(IO,_LVDS2N_14N,_DQ2) ; also on sheet 23
MEM_DQB18: U1.D38(IO,_LVDS2N_14P,_DQ2) ; also on sheet 23
MEM_DQB19: U1.E37(IO,_LVDS2N_17P,_DQ2) ; also on sheet 23
MEM_DQB20: U1.D35(IO,_PLL_2N_CLKOUT0N,_LVDS2N_15N,_DQ2) ; also on sheet 23
MEM_DQB21: U1.D39(IO,_CLK_2N_0N,_LVDS2N_13N,_DQ2) ; also on sheet 23
MEM_DQB22: U1.E39(IO,_CLK_2N_0P,_LVDS2N_13P,_DQ2) ; also on sheet 23
MEM_DQB23: U1.H37(IO,_LVDS2N_18N,_DQ2) ; also on sheet 23
MEM_DQB24: U1.A37(IO,_LVDS2N_24N,_DQ3) ; also on sheet 23
MEM_DQB25: U1.B38(IO,_LVDS2N_23N,_DQ3) ; also on sheet 23
MEM_DQB26: U1.C38(IO,_LVDS2N_23P,_DQ3) ; also on sheet 23
MEM_DQB27: U1.A38(IO,_LVDS2N_24P,_DQ3) ; also on sheet 23
MEM_DQB28: U1.C37(IO,_LVDS2N_21P,_DQ3) ; also on sheet 23
MEM_DQB29: U1.B37(IO,_LVDS2N_21N,_DQ3) ; also on sheet 23
MEM_DQB30: U1.B35(IO,_LVDS2N_20P,_DQ3) ; also on sheet 23
MEM_DQB31: U1.C35(IO,_LVDS2N_20N,_DQ3) ; also on sheet 23
MEM_DQB32: U1.J36(IO,_RZQ_2N,_LVDS2N_11P,_DQ1) ; also on sheet 23
MEM_DQB33: U1.D36(IO,_LVDS2N_19P,_DQ3) ; also on sheet 23
MEM_DQS_ADDR_CMD_N: U1.T32(IO,_LVDS2M_4N,_DQSN4) ; also on sheet 23
MEM_DQS_ADDR_CMD_P: U1.R32(IO,_LVDS2M_4P,_DQS4) ; also on sheet 23
MEM_DQSA_N0: U1.F26(IO,_LVDS2L_4N,_DQSN8) ; also on sheet 23
MEM_DQSA_N1: U1.K26(IO,_PLL_2L_CLKOUT1N,_LVDS2L_10N,_DQSN9) ; also on sheet 23
MEM_DQSA_N2: U1.V27(IO,_LVDS2L_16N,_DQSN10) ; also on sheet 23
MEM_DQSA_N3: U1.R27(IO,_LVDS2L_22N,_DQSN11) ; also on sheet 23
MEM_DQSA_P0: U1.E26(IO,_LVDS2L_4P,_DQS8) ; also on sheet 23
MEM_DQSA_P1: U1.J26(IO,_PLL_2L_CLKOUT1P,_PLL_2L_CLKOUT1,_PLL_2L_FBN,_LVDS2L_10P,_DQS9) ; also on sheet 23
MEM_DQSA_P2: U1.V28(IO,_LVDS2L_16P,_DQS10) ; also on sheet 23
MEM_DQSA_P3: U1.T26(IO,_LVDS2L_22P,_DQS11) ; also on sheet 23
MEM_DQSB_N0: U1.L31(IO,_LVDS2N_4N,_DQSN0) ; also on sheet 23
MEM_DQSB_N1: U1.G34(IO,_PLL_2N_CLKOUT1N,_LVDS2N_10N,_DQSN1) ; also on sheet 23
MEM_DQSB_N2: U1.F36(IO,_LVDS2N_16N,_DQSN2) ; also on sheet 23
MEM_DQSB_N3: U1.A35(IO,_LVDS2N_22N,_DQSN3) ; also on sheet 23
MEM_DQSB_P0: U1.L32(IO,_LVDS2N_4P,_DQS0) ; also on sheet 23
MEM_DQSB_P1: U1.G33(IO,_PLL_2N_CLKOUT1P,_PLL_2N_CLKOUT1,_PLL_2N_FBN,_LVDS2N_10P,_DQS1) ; also on sheet 23
MEM_DQSB_P2: U1.E36(IO,_LVDS2N_16P,_DQS2) ; also on sheet 23
MEM_DQSB_P3: U1.A36(IO,_LVDS2N_22P,_DQS3) ; also on sheet 23
MEM_QKA_P0: U1.C25(IO,_LVDS2L_6P,_DQ8) ; also on sheet 23
MEM_QKA_P1: U1.T27(IO,_LVDS2L_18P,_DQ10) ; also on sheet 23
MEM_QKB_P0: U1.L34(IO,_LVDS2N_6P,_DQ0) ; also on sheet 23
MEM_QKB_P1: U1.G37(IO,_LVDS2N_18P,_DQ2) ; also on sheet 23
MSEL1: SW1.5 U1.BE22(SDM_IO7,_AS_NCSO2,_NAND_ALE,MSEL1) ; also on sheet 19
MSEL2: SW1.2 U1.BH22(SDM_IO9,_AS_NCSO1,_NAND_CLE,_MSEL2) ; also on sheet 19
PCIE_PERSTn: D46.2(A) U1.AJ34(IO3V0_10,_NPERSTL0) ; also on sheet 17
PCIE_SMBCLK: U1.AU33(IO,_LVDS2B_24N,_DQ43) ; also on sheet 17
PCIE_SMBDAT: U1.AV35(IO,_LVDS2B_23P,_DQ43) ; also on sheet 17
PCIE_WAKEn: U1.AU34(IO,_LVDS2B_24P,_DQ43) ; also on sheet 17
QSFP1_INTERRUPTn: U1.BE26(IO,_LVDS2F_20P,_DQ35) ; also on sheet 27
QSFP1_LP_MODE: U1.BD26(IO,_LVDS2F_20N,_DQ35) ; also on sheet 27
QSFP1_MOD_PRSn: U1.BF27(IO,_LVDS2F_21N,_DQ35) ; also on sheet 27
QSFP1_MOD_SELn: U1.BF26(IO,_LVDS2F_19N,_DQ35) ; also on sheet 27
QSFP1_RSTn: U1.BE27(IO,_LVDS2F_19P,_DQ35) ; also on sheet 27
QSFP_SCL: U1.BJ26(IO,_LVDS2F_24P,_DQ35) ; also on sheet 27
QSFP_SDA: U1.BH27(IO,_LVDS2F_24N,_DQ35) ; also on sheet 27
QSPI_CLK: R10.2 U2.B2(C)
QSPI_IO0: U1.AN23(SDM_IO4,_AVSTX8_DATA1,_AS_DATA0,_SDMMC_CFG_CMD,_NAND_ADQ1) U2.D3(DQ0)
QSPI_IO1: U1.BB22(SDM_IO1,_AVSTX8_DATA2,AS_DATA1,SDMMC_CFG_DATA1,NAND_RE_N) U2.D2(DQ1)
QSPI_IO2: U1.BB23(SDM_IO3,_AVSTX8_DATA3,_AS_DATA2,_SDMMC_CFG_DATA2,_NAND_ADQ2) U2.C4(W#/VPP/DQ2)
QSPI_IO3: U1.BA24(SDM_IO6,_AVSTX8_DATA4,_AS_DATA3,_SDMMC_CFG_DATA3,_NAND_ADQ3) U2.D4(HOLD#/DQ3)
QSPI_SS0_MSEL0: R15.1 U1.BC23(SDM_IO5,_AS_NCSO0,_SDMMC_CFG_CCLK,_NAND_WE_N,_MSEL0,_CONF_DONE) U2.C2(S#) ; also on sheet 19
RZQ_B2M: U1.P34(IO,_RZQ_2M,_LVDS2M_11P,_DQ5) ; also on sheet 29
S10_JTAG_TCK: R11.1 U1.AN22(TCK) ; also on sheet 30
S10_JTAG_TDI: R3.2 U1.AR22(TDI) ; also on sheet 30
S10_JTAG_TDO: U1.BD24(TDO) ; also on sheet 30
S10_JTAG_TMS: R4.2 U1.BC22(TMS) ; also on sheet 30
S10_VCC_SENSE: R5370.1 ; also on sheet 15 35
S10_VCCIO_FMCA: C4.1 R25.2 R26.2 R31.2 R32.2 ; also on sheet 15 25 31 41 45
SDI_MF0_BYPASS: U1.BA40(IO,_LVDS2C_1P,_DQ36) ; also on sheet 19 28
SDI_MF1_AUTO_SLEEP: U1.BA39(IO,_LVDS2C_2N,_DQ36) ; also on sheet 19 28
SDI_MF2_MUTE: U1.BB39(IO,_LVDS2C_2P,_DQ36) ; also on sheet 19 28
SDI_TX_SD_HDn: U1.AY40(IO,_LVDS2C_1N,_DQ36) ; also on sheet 19 28
U0A_VDD33: C831.1 U84.1(ENABLE) U84.2(DISCEN) U84.12(VCC) ; also on sheet 31
USB_ADDR0: U1.AB35(IO3V6_12) ; also on sheet 30
USB_ADDR1: U1.AB36(IO3V7_12) ; also on sheet 30
USB_DATA0: U1.AE14(IO3V0_22,_NPERSTR2) ; also on sheet 30
USB_DATA1: U1.AD15(IO3V1_22) ; also on sheet 30
USB_DATA2: U1.AC15(IO3V2_22) ; also on sheet 30
USB_DATA3: U1.AC14(IO3V3_22) ; also on sheet 30
USB_DATA4: U1.AB13(IO3V4_22) ; also on sheet 30
USB_DATA5: U1.AD14(IO3V5_22) ; also on sheet 30
USB_DATA6: U1.AB15(IO3V6_22) ; also on sheet 30
USB_DATA7: U1.AB14(IO3V7_22) ; also on sheet 30
USB_EMPTY: U1.AF15(IO3V1_20) ; also on sheet 30
USB_FPGA_CLK: U1.AW36(IO,_CLK_2B_0P,_LVDS2B_13P,_DQ42) ; also on sheet 30
USB_FULL: U1.AH16(IO3V0_20,_NPERSTR0) ; also on sheet 30
USB_OEn: U1.AD16(IO3V4_20) ; also on sheet 30
USB_RDn: U1.AF16(IO3V5_20) ; also on sheet 30
USB_RESETn: U1.AH17(IO3V7_20) ; also on sheet 30
USB_SCL: U1.AB12(IO3V2_20) ; also on sheet 30
USB_SDA: U1.AF17(IO3V3_20) ; also on sheet 30
USB_WRn: U1.AE16(IO3V6_20) ; also on sheet 30
VREF_1.25VADC: C1.1 D1.6(VOUT) R12.1 V1.2(SNS)
N16953782: R13.1 SW1.1
N16953787: R16.2 SW1.3
N16953883: R14.1 SW1.4
N16953888: R17.2 SW1.6
N16956651: R5.1 U1.AF38(RREF_BL)
N16956654: R6.1 U1.AD38(RREF_TL)
N16956657: R7.1 U1.AD12(RREF_TR)
N16956660: R8.1 U1.AF12(RREF_BR)
N17757463: R32.1 U3.8(FAULTn)
N17757467: R31.1 U3.7(READY)
N17960721: R9.1 U1.BJ23(RREF_SDM)
N18104851: R22.2 U1.AP30(IO,_RZQ_2F,_LVDS2F_11P,_DQ33)
N18169549: R10.1 U1.BE23(SDM_IO2,_AVSTX8_DATA0,_AS_CLK)
N19240018: R24.1 U1.AV21(IO,_RZQ_3C,_LVDS3C_11P,_DQ85)
N20199044: R21.1 U1.BB35(IO,_PLL_2B_CLKOUT0P,_PLL_2B_CLKOUT0,_PLL_2B_FBP,_PLL_2B_FB0,_LVDS2B_15P,_DQ42)
N20255236: R18.2 U1.AY31(IO,_RZQ_2A,_LVDS2A_11P,_DQ45)
N20255553: R20.2 U1.BJ35(IO,_RZQ_2B,_LVDS2B_11P,_DQ41)
N20255921: R19.2 U1.BF40(IO,_RZQ_2C,_LVDS2C_11P,_DQ37)
N21439132: R5290.1 U84.8(FAULTn)
N21439136: R5289.1 U84.7(READY)

Not connected (* = marked no-connect by the designer): D1 1(NC1)* 2(NC2)* 3(NC3)* 7(NC7)* 8(NC8)*; U1 AC33(IO3V4_12)* AC36(IO3V5_12)* AE36(IO3V4_10)* AF34(IO3V3_10)* AG34(IO3V5_10)* AG35(IO3V1_10)* AH32(IO3V6_10)* AH33(IO3V2_10)* AJ33(IO3V7_10)* AN21(IO,_PLL_3C_CLKOUT1P,_PLL_3C_CLKOUT1,_PLL_3C_FBN,_LVDS3C_10P,_DQS85)* AN33(IO,_LVDS2C_21P,_DQ39)* AP12(IO,_LVDS3B_4P,_DQS88)* AP21(IO,_PLL_3C_CLKOUT1N,_LVDS3C_10N,_DQSN85)* AP28(IO,_LVDS2F_9P,_DQ33)* AP29(IO,_LVDS2F_9N,_DQ33)* AP31(IO,_LVDS2F_11N,_DQ33)* AP33(IO,_LVDS2C_21N,_DQ39)* AP34(IO,_LVDS2C_24P,_DQ39)* AP35(IO,_LVDS2C_19P,_DQ39)* AP36(IO,_LVDS2C_20P,_DQ39)* AR13(IO,_LVDS3B_4N,_DQSN88)* AR26(IO,_LVDS2F_4P,_DQS32)* AR27(IO,_PLL_2F_CLKOUT1N,_LVDS2F_10N,_DQSN33)* AR28(IO,_PLL_2F_CLKOUT1P,_PLL_2F_CLKOUT1,_PLL_2F_FBN,_LVDS2F_10P,_DQS33)* AR31(IO,_LVDS2B_22N,_DQSN43)* AR32(IO,_LVDS2B_22P,_DQS43)* AR33(IO,_LVDS2C_24N,_DQ39)* AR34(IO,_LVDS2C_19N,_DQ39)* AR36(IO,_LVDS2C_20N,_DQ39)* AR37(IO,_LVDS2C_23N,_DQ39)* AT26(IO,_LVDS2F_4N,_DQSN32)* AT32(IO,_LVDS2B_19N,_DQ43)* AT35(IO,_LVDS2B_21P,_DQ43)* AT36(IO,_LVDS2C_22N,_DQSN39)* AT37(IO,_LVDS2C_22P,_DQS39)* AT38(IO,_LVDS2C_23P,_DQ39)* AU32(IO,_LVDS2B_19P,_DQ43)* AU35(IO,_LVDS2B_23N,_DQ43)* AU37(IO,_LVDS2C_17N,_DQ38)* AU38(IO,_LVDS2C_17P,_DQ38)* AV15(IO,_CLK_3A_0N,_LVDS3A_13N,_DQ94,_AVST_DATA22)* AV16(IO,_LVDS3A_19P,_DQ95)* AV17(IO,_LVDS3A_19N,_DQ95)* AV18(IO,_LVDS3A_22N,_DQSN95)* AV20(IO,_LVDS3C_11N,_DQ85)* AV26(IO,_LVDS2F_3N,_DQ32)* AV27(IO,_LVDS2F_3P,_DQ32)* AV36(IO,_CLK_2B_0N,_LVDS2B_13N,_DQ42)* AV37(IO,_LVDS2C_18P,_DQ38)* AV38(IO,_LVDS2C_18N,_DQ38)* AV40(IO,_PLL_2C_CLKOUT0N,_LVDS2C_15N,_DQ38)* AW14(IO,_PLL_3A_CLKOUT0N,_LVDS3A_15N,_DQ94,_AVST_DATA26)* AW15(IO,_CLK_3A_0P,_LVDS3A_13P,_DQ94,_AVST_DATA23)* AW16(IO,_LVDS3A_21P,_DQ95)* AW18(IO,_LVDS3A_22P,_DQS95)* AW21(IO,_LVDS3C_4P,_DQS84)* AW24(SDM_IO13,_AVSTX8_DATA5,_SDMMC_CFG_DATA5,_NAND_CE_N)* AW30(IO,_CLK_2A_1P,_LVDS2A_12P,_DQ45)* AW31(IO,_CLK_2A_1N,_LVDS2A_12N,_DQ45)* AW33(IO,_LVDS2B_14P,_DQ42)* AW34(IO,_LVDS2B_16P,_DQS42)* AW35(IO,_LVDS2B_16N,_DQSN42)* AW38(IO,_CLK_2C_0P,_LVDS2C_13P,_DQ38)* AW39(IO,_CLK_2C_0N,_LVDS2C_13N,_DQ38)* AW40(IO,_PLL_2C_CLKOUT0P,_PLL_2C_CLKOUT0,_PLL_2C_FBP,_PLL_2C_FB0,_LVDS2C_15P,_DQ38)* AY14(IO,_PLL_3A_CLKOUT0P,_PLL_3A_CLKOUT0,_PLL_3A_FBP,_PLL_3A_FB0,_LVDS3A_15P,_DQ94,_AVST_DATA27)* AY17(IO,_LVDS3A_20P,_DQ95)* AY18(IO,_LVDS3A_24N,_DQ95)* AY21(IO,_LVDS3C_4N,_DQSN84)* AY24(SDM_IO10,_AVSTX8_DATA7,_SDMMC_CFG_DATA7,_NAND_ADQ5)* AY27(IO,_LVDS2F_17N,_DQ34)* AY28(IO,_LVDS2F_17P,_DQ34)* AY33(IO,_LVDS2B_14N,_DQ42)* AY37(IO,_LVDS2C_14P,_DQ38)* AY38(IO,_LVDS2C_16P,_DQS38)* AY39(IO,_LVDS2C_16N,_DQSN38)* BA14(IO,_LVDS3A_16P,_DQS94,_AVST_DATA29)* BA15(IO,_LVDS3A_14N,_DQ94,_AVST_DATA24)* BA16(IO,_LVDS3A_14P,_DQ94,_AVST_DATA25)* BA20(IO,_LVDS3C_1P,_DQ84)* BA21(IO,_LVDS3C_1N,_DQ84)* BA25(IO,_LVDS2F_14P,_DQ34)* BA26(IO,_CLK_2F_0N,_LVDS2F_13N,_DQ34)* BA27(IO,_CLK_2F_0P,_LVDS2F_13P,_DQ34)* BA35(IO,_PLL_2B_CLKOUT0N,_LVDS2B_15N,_DQ42)* BA37(IO,_LVDS2C_14N,_DQ38)* BB13(IO,_LVDS3A_18N,_DQ94)* BB14(IO,_LVDS3A_16N,_DQSN94,_AVST_DATA28)* BB15(IO,_LVDS3A_17N,_DQ94,_AVST_DATA30)* BB17(IO,_LVDS3A_23P,_DQ95)* BB20(IO,_LVDS3C_2N,_DQ84)* BB25(IO,_LVDS2F_14N,_DQ34)* BB27(IO,_PLL_2F_CLKOUT0N,_LVDS2F_15N,_DQ34)* BB37(IO,_LVDS2C_6P,_DQ36)* BB38(IO,_LVDS2C_5P,_DQ36)* BB40(IO,_LVDS2C_3N,_DQ36)* BC15(IO,_LVDS3A_17P,_DQ94,_AVST_DATA31)* BC17(IO,_LVDS3A_23N,_DQ95)* BC20(IO,_LVDS3C_2P,_DQ84)* BC21(IO,_LVDS3C_3P,_DQ84)* BC25(IO,_LVDS2F_16N,_DQSN34)* BC26(IO,_LVDS2F_16P,_DQS34)* BC27(IO,_PLL_2F_CLKOUT0P,_PLL_2F_CLKOUT0,_PLL_2F_FBP,_PLL_2F_FB0,_LVDS2F_15P,_DQ34)* BC28(IO,_LVDS2F_18P,_DQ34)* BC37(IO,_LVDS2C_6N,_DQ36)* BC38(IO,_LVDS2C_5N,_DQ36)* BC40(IO,_LVDS2C_3P,_DQ36)* BD19(IO,_PLL_3C_CLKOUT0P,_PLL_3C_CLKOUT0,_PLL_3C_FBP,_PLL_3C_FB0,_LVDS3C_15P,_DQ86)* BD20(IO,_PLL_3C_CLKOUT0N,_LVDS3C_15N,_DQ86)* BD21(IO,_LVDS3C_3N,_DQ84)* BD28(IO,_LVDS2F_18N,_DQ34)* BD29(IO,_LVDS2A_14P,_DQ46)* BD31(IO,_CLK_2A_0N,_LVDS2A_13N,_DQ46)* BD38(IO,_LVDS2C_4N,_DQSN36)* BD39(IO,_LVDS2C_4P,_DQS36)* BD40(IO,_LVDS2C_7N,_DQ37)* BE29(IO,_LVDS2A_14N,_DQ46)* BE31(IO,_CLK_2A_0P,_LVDS2A_13P,_DQ46)* BE32(IO,_LVDS2A_23P,_DQ47)* BE33(IO,_PLL_2B_CLKOUT1P,_PLL_2B_CLKOUT1,_PLL_2B_FBN,_LVDS2B_10P,_DQS41)* BE34(IO,_PLL_2B_CLKOUT1N,_LVDS2B_10N,_DQSN41)* BE37(IO,_PLL_2C_CLKOUT1N,_LVDS2C_10N,_DQSN37)* BE38(IO,_LVDS2C_9N,_DQ37)* BE39(IO,_LVDS2C_9P,_DQ37)* BE40(IO,_LVDS2C_7P,_DQ37)* BF20(IO,_LVDS3C_14P,_DQ86)* BF30(IO,_PLL_2A_CLKOUT0N,_LVDS2A_15N,_DQ46)* BF32(IO,_LVDS2A_23N,_DQ47)* BF37(IO,_PLL_2C_CLKOUT1P,_PLL_2C_CLKOUT1,_PLL_2C_FBN,_LVDS2C_10P,_DQS37)* BF39(IO,_LVDS2C_11N,_DQ37)* BG13(IO,_LVDS3A_9N,_DQ93,_AVST_DATA16)* BG14(IO,_LVDS3A_9P,_DQ93,_AVST_DATA17)* BG18(IO,_LVDS3C_19P,_DQ87)* BG19(IO,_LVDS3C_19N,_DQ87)* BG20(IO,_LVDS3C_14N,_DQ86)* BG25(IO,_LVDS2F_23N,_DQ35)* BG27(IO,_LVDS2F_21P,_DQ35)* BG32(IO,_LVDS2A_24N,_DQ47)* BG33(IO,_CLK_2B_1N,_LVDS2B_12N,_DQ41)* BG35(IO,_LVDS2B_9N,_DQ41)* BG37(IO,_LVDS2C_8P,_DQ37)* BG38(IO,_LVDS2C_8N,_DQ37)* BH12(IO,_LVDS3A_11N,_DQ93)* BH15(IO,_PLL_3A_CLKOUT1N,_LVDS3A_10N,_DQSN93,_AVST_DATA18)* BH16(IO,_CLK_3A_1N,_LVDS3A_12N,_DQ93,_AVST_DATA20)* BH25(IO,_LVDS2F_22N,_DQSN35)* BH26(IO,_LVDS2F_23P,_DQ35)* BH31(IO,_LVDS2A_22P,_DQS47)* BH32(IO,_LVDS2A_24P,_DQ47)* BH35(IO,_LVDS2B_9P,_DQ41)* BH36(IO,_CLK_2C_1P,_LVDS2C_12P,_DQ37)* BH37(IO,_CLK_2C_1N,_LVDS2C_12N,_DQ37)* BJ15(IO,_PLL_3A_CLKOUT1P,_PLL_3A_CLKOUT1,_PLL_3A_FBN,_LVDS3A_10P,_DQS93,_AVST_DATA19)* BJ16(IO,_CLK_3A_1P,_LVDS3A_12P,_DQ93,_AVST_DATA21)* BJ25(IO,_LVDS2F_22P,_DQS35)* BJ36(IO,_LVDS2B_11N,_DQ41)*; U2 A2(NC1)* A3(NC2)* A4(NC3)* A5(NC4)* B1(NC5)* B5(NC6)* C1(NC7)* C3(NC8)* C5(NC9)* D1(NC10)* D5(NC11)* E1(NC12)* E2(NC13)* E3(NC14)* E4(NC15)* E5(NC16)*

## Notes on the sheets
sheet 1
- NOTES:
- REV
- DATE
- PAGES
- DESCRIPTION
- 1.
- Project Drawing Numbers:
       Raw PCB
       Gerber Files
       PCB Design Files
       Assembly Drawing
       Fab Drawing
       Schematic Drawing
       PCB Film
       Bill of Materials
       Schematic Design Files
       Functional Specification
       PCB Layout Guidelines
       Assembly Rework
- A1
- 03/31/2016
- All
- Initial Release
- 100-0321309-D1
  110-0321309-D1
  120-0321309-D1
  130-0321309-D1
  140-0321309-D1
  150-0321309-D1
  160-0321309-D1
  170-0321309-D1
  180-0321309-D1
  210-0321309-D1
  220-0321309-D1
  320-0321309-D1
- B1
- C1
- 06/15/2016
- 12/1/2016
- 06
- 06
- Fix MSEL1 unconnection
- Remove R5372 and change R5373 to 0-ohm
- 19
- Add U86.  Move I2C_SCL/SDA from U85 to U86
- 28
- Update SDI BOM stuffing options for 12Gbps. Replace R164 and R165 with C873 and C874.
- 30
- Add R5382, R5383 to source USB_MAX5_CLK and USB_FPGA_CLK from U23 instead of U27
- 31
- Add C872 to I2C_SCL signal near SW8.2 to GND to clean glitch
- 33
- Remove power-on switch SW7.6 connection to GND
- 38
- 40
- Add C866-C868 (100uF) for VCCT_GXB & move C454-C456 before R432
- Change C428 to Conflict Mineral Free part
- 40
- Add C869-C871 (100uF) for VCCR_GXB & move C458-C460 before R436
- 40
- Change R437 to 169K for 700Khz switching frequency
- 15,32
- Connect core TEMPDIODE to MAX1619
- 32
- Add dedicated LDO (U87) for MAX1619 power.
  Connect MAX1619 OVERTEMPn to LT2987 CTRL1 to power of when overtemp occurs.
- 15
- 32
- Update note on pg 15 regarding TEMPSENSE pins
- D1
- 3/2/2017
- PAGE
- DESCRIPTION
- PAGE
- DESCRIPTION
- 1
- Title, Note, Block Diagram
- 37
- Power - VCC part 3
- 2
- Power Tree Diagram
- 38
- Power - VCCRAM
- 3
- Power Sequence Diagram
- 39
- Power - VCCPT & 1.8V
- 4
- I2C & JTAG Diagram
- 40
- Power - VCCR_GXB, VCCT_GXB
- 5
- Clock Diagram
- 41
- Power - FMCA, FMCB
- 6
- S10 GX Configuration
- 42
- Power - HILO MEMORY
- 7
- S10 GX Bank 2A,B,C
- 43
- Power - 5V, 2.5V, 2.4V, 1V
- 8
- S10 GX Bank 2F,L,M,N
- 44
- Power - VCCIO3V
- 9
- S10 GX Bank 3A,B,C
- 45
- S10 Decoupling
- 10
- S10 GX Bank 3I,J,K,L
- 46
- Fast Power-Down Discharge
- 11
- S10 GX Xcvr GXBL 1C,D,E,F
- 47
- 12
- S10 GX Xcvr GXBL 1K,L,M,N
- 48
- 13
- S10 GX Xcvr GXBR 4C,D,E,F
- 49
- 14
- S10 GX Xcvr GXBR 4K,L,M,N
- 50
- 15
- S10 GX Power
- 51
- 16
- S10 GX Ground
- 52
- 17
- PCIe Edge Gold Fingers
- 53
- 18
- Board System Clocks
- 54
- 19
- MaxV System Controller
- 55
- 20
- Flash Memory
- 56
- 21
- 10/100/1000 Ethernet Phy
- 57
- 22
- HILO Connector Map
- 58
- 23
- HILO Memory Interface
- 59
- 24
- Display Port (x4)
- 60
- 25
- FMC Port A
- 61
- 26
- Blank
- 62
- 27
- QSFP
- 63
- 28
- 12G SDI
- 64
- 29
- LCD, User PB, SW, I/Os
- 65
- 30
- Max10 USB Blaster II
- 66
- 31
- LT2987 Power Seq
- 67
- 32
- Current & Temp Sense
- 68
- 33
- Power - Select Power Input
- 69
- 34
- Power - 12V-3.3V_REG, 3.3V
- 70
- 35
- Power - VCC part 1
- 71
- 36
- Power - VCC part 2
- 72
sheet 2
- Power Tree Diagram
sheet 3
- Power Sequence Diagram
- *Power-down sequence is the reverse of power-up sequence
sheet 4
- I2C & JTAG Diagram
- I2C
- JTAG
sheet 5
- Clock Diagram
sheet 6
- S10 GX Configuration
- AVST_READY must be double
  registered inside MAXV for
  syncronization to AVST_CLK
- Dedicated 3V I/O Bank
- For Active Serial Configuration
- Config Mode
- MSEL2
- MSEL1
- MSEL0
- Comments
- AVST x32
- 0
- 0
- 0
- Not Supported
- USB
  Blaster
  II
- AS Fast
- 0
- 0
- 1
- QSPI Support
- Nand x8
- 0
- 1
- 0
- Not Supported
- AS Normal
- 0
- 1
- 1
- Supported
- ENET MGMT
- AVST x16
- SD/MMC x4
- 1
- 1
- 0
- 0
- 0
- 1
- Default Mode
- Not Supported
- AVST x8
- 1
- 1
- 0
- Not Supported
- JTAG only
- 1
- 1
- 1
- Supported
- USB Blaster II
- H = 1.30mm
  Place on Bottom side
- H = 1.10mm
  Place on Bottom side
sheet 7
- S10 GX Bank 2A, B, C
- PCIE Sideband Signals
- Clocks
- SDI CONTROLS
- 1.8V
- 1.8V
- 1.8V
sheet 8
- S10 GX Bank 2F, L, M, N
- QSFP INTERFACE
- ENET SGMII
- ENET SGMII
- Display Port
- Clocks
- HILO Cmd/Addr/Ctrl
- ADJ: 1.2V, 1.25V,
  1.35V, 1.5V, 1.8V
- 1.8V
- No Swap Allowed for this
  entire Address/Command Group
- HILO MEMORY INTERFACE
- QSFP
- HILO Byte Group 0A
- No Swap Allowed
- No Swap Allowed
- HILO Byte Group 0B
- No Swap Allowed
- No Swap Allowed
- QDR4 QKA_P0 -->
- No Swap Allowed
- No Swap Allowed
- <-- QDR4 QKB_P0
- No Swap Allowed
- No Swap Allowed
- HILO Byte Group 1A
- No Swap Allowed
- No Swap Allowed
- HILO Byte Group 1B
- No Swap Allowed
- No Swap Allowed
- ADJ: 1.2V, 1.25V,
  1.35V, 1.5V, 1.8V
- ADJ: 1.2V, 1.25V,
  1.35V, 1.5V, 1.8V
- No Swap Allowed
- No Swap Allowed
- DISPLAY PORT INTERFACE
- No Swap Allowed
- No Swap Allowed
- No Swap Allowed
- No Swap Allowed
- HILO Byte Group 2A
- No Swap Allowed
- No Swap Allowed
- HILO Byte Group 2B
- No Swap Allowed
- No Swap Allowed
- QDR4 QKA_P1 -->
- No Swap Allowed
- No Swap Allowed
- <-- QDR4 QKB_P1
- No Swap Allowed
- No Swap Allowed
- No Swap Allowed
- No Swap Allowed
- HILO Byte Group 3A
- No Swap Allowed
- No Swap Allowed
- HILO Byte Group 3B
- No Swap Allowed
- No Swap Allowed
sheet 9
- S10 GX Bank 3A, B, C
- FMCA INTERFACE
- AVSTx32 CONFIG DATA INTERFACE
- 1.8V
- 1.2V,1.35V,
  1.5V, 1.8V
- FMCA I/Os
- PARTIAL RECONFIG SIGNALS
- 1.2V,1.35V,
  1.5V, 1.8V
- FMCA I/Os
- H = 1.10mm
  Place on Bottom side
